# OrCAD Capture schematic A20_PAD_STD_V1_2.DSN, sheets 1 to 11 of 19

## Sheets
1 P11: POWER2: size A3; title: A20_PAD_STD; rev: V1.2; note: POWER2
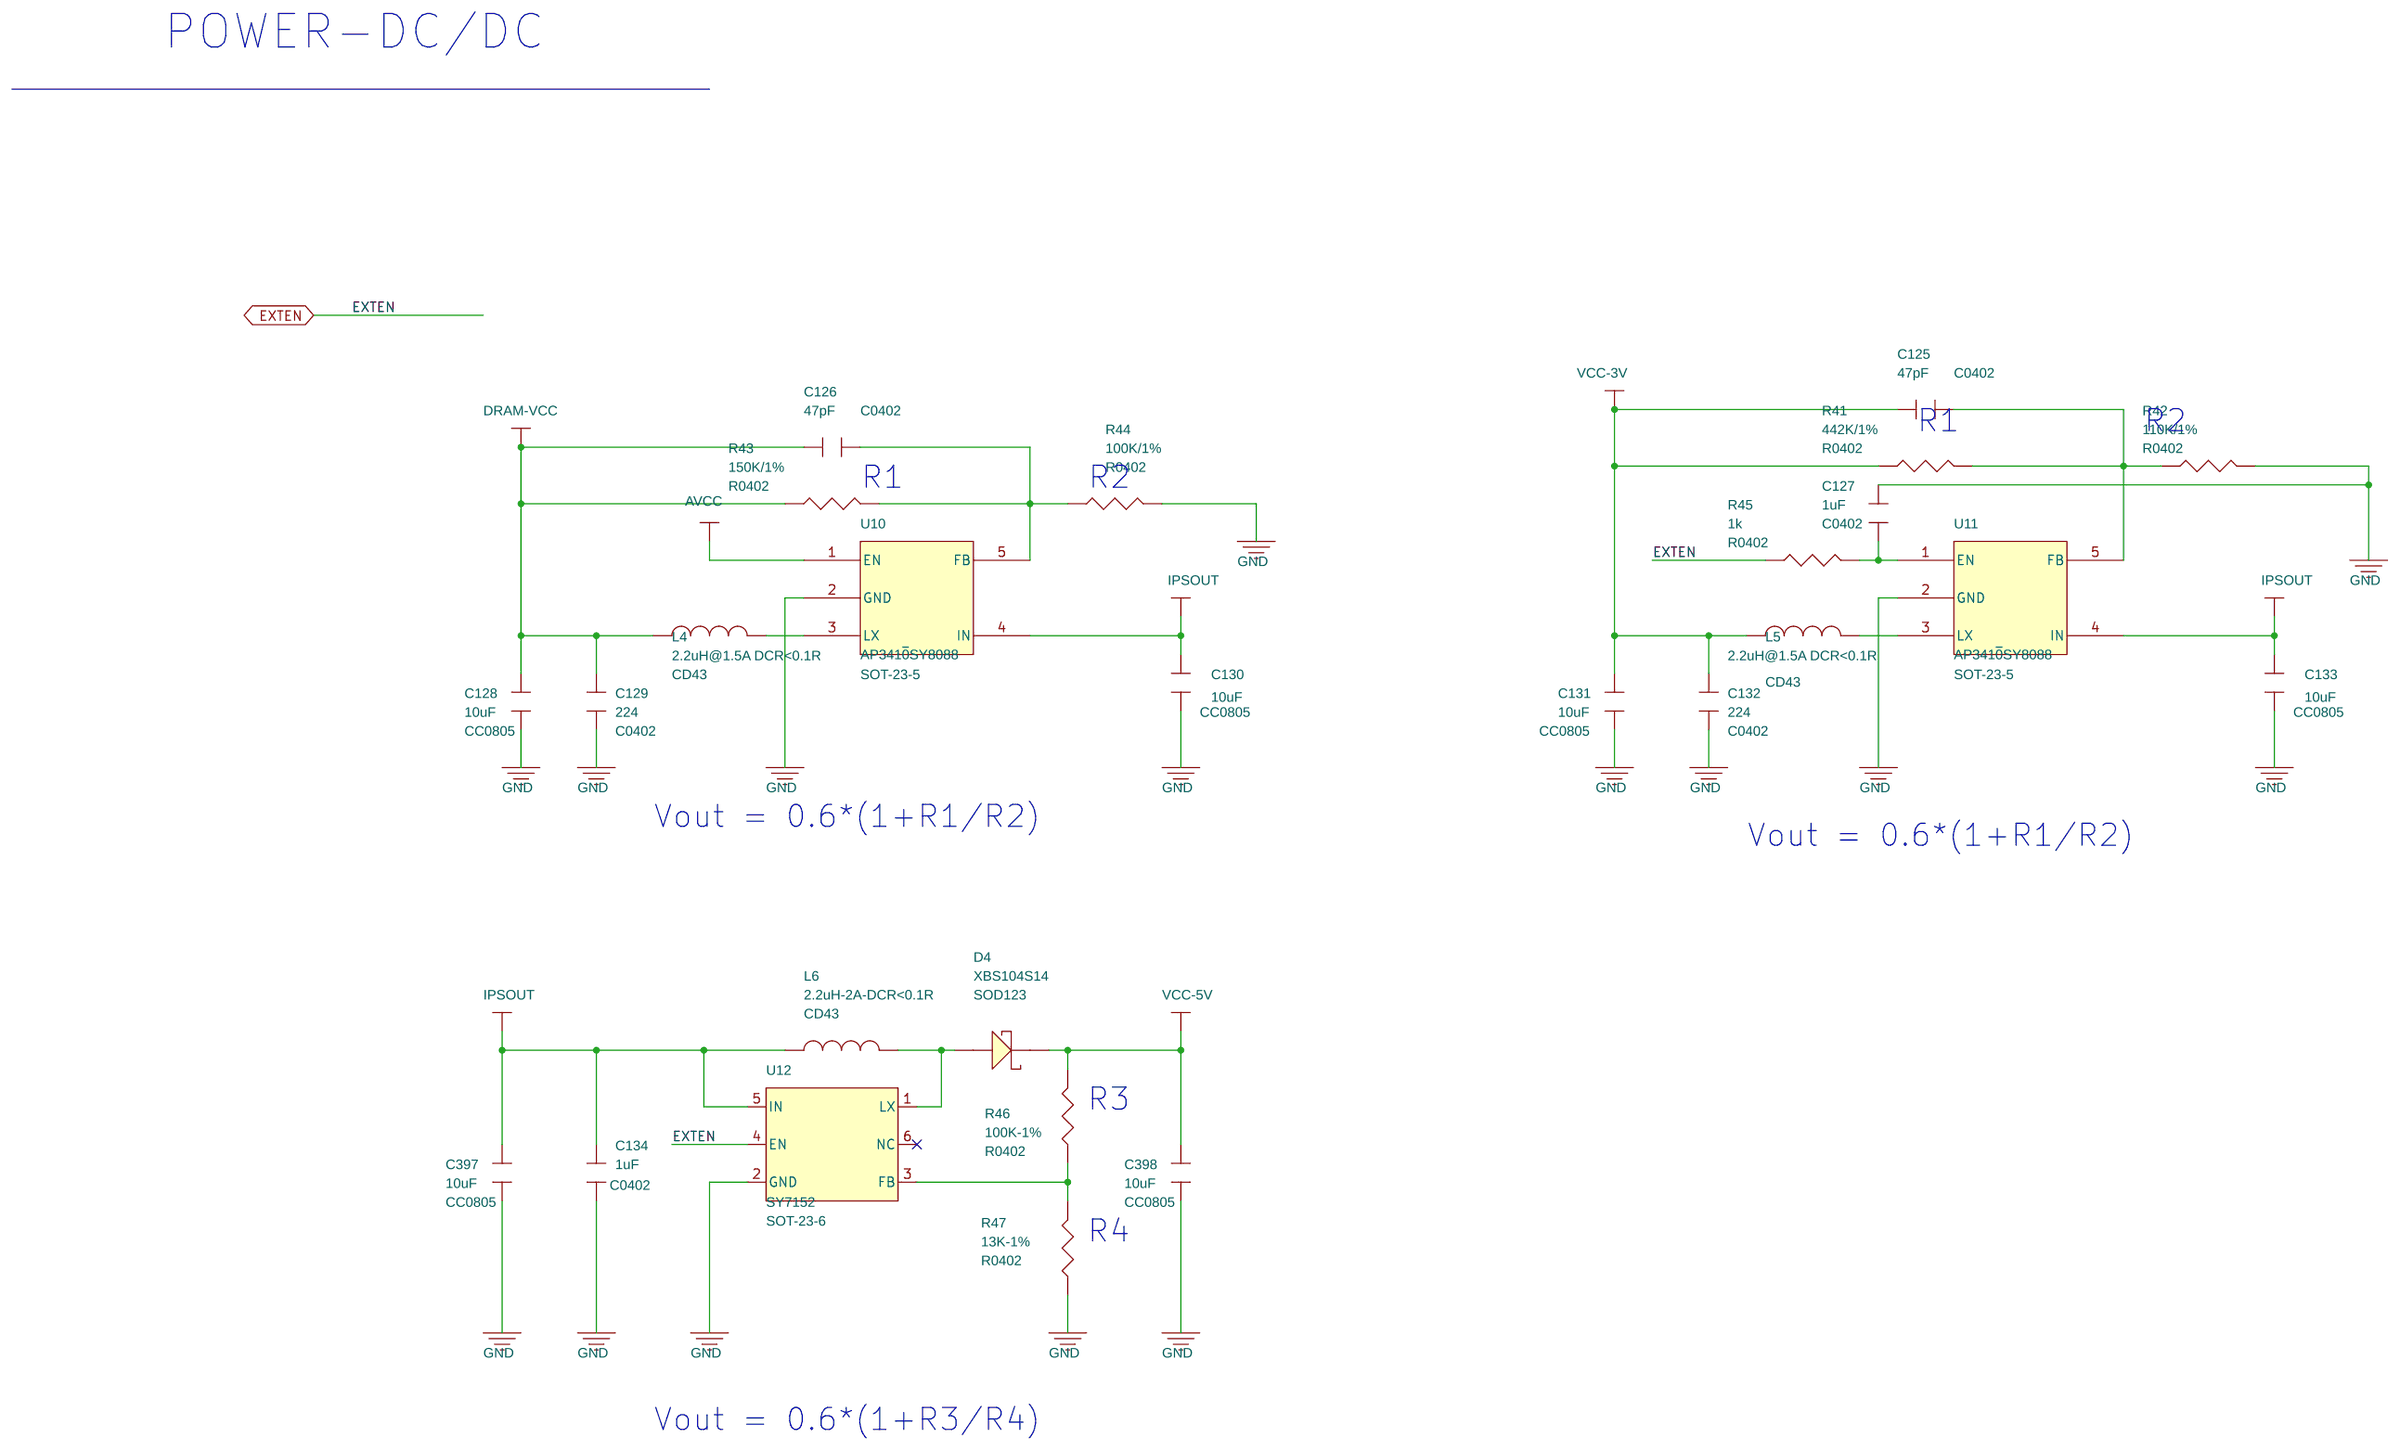
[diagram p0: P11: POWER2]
2 P06: CPU2: size A3; note: CPU2
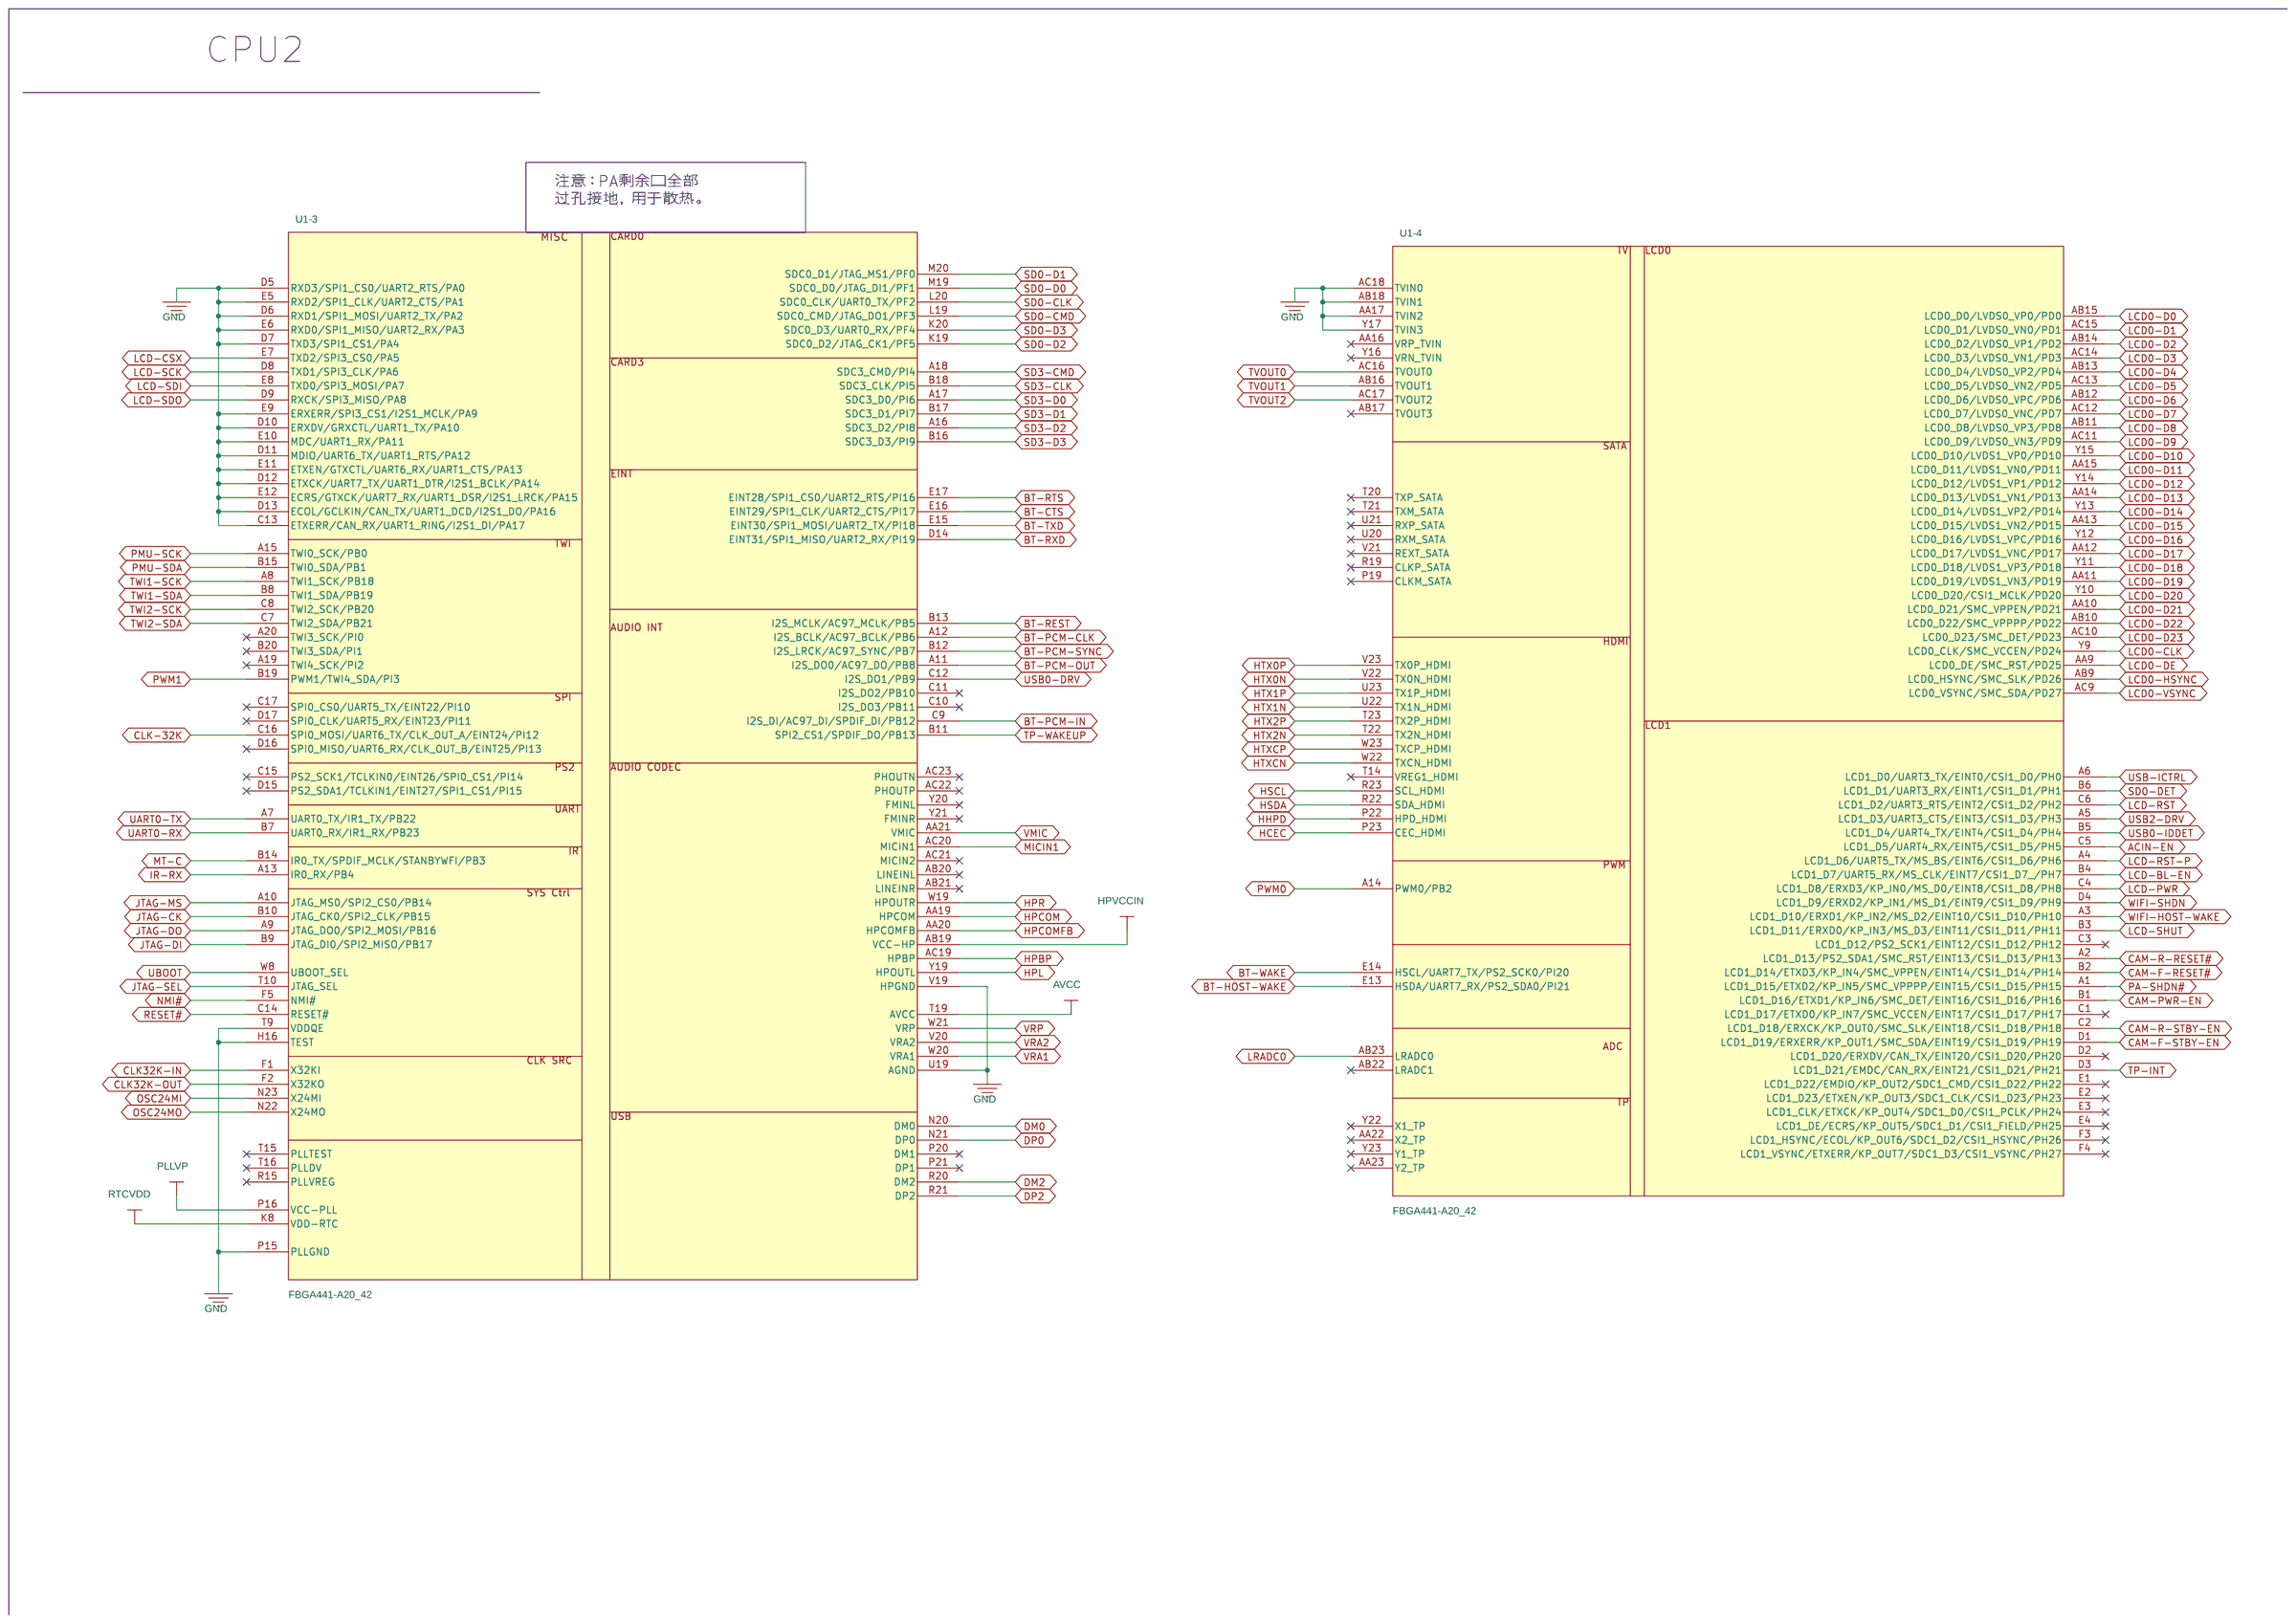
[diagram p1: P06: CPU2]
3 P18: USB: size A3; note: USB
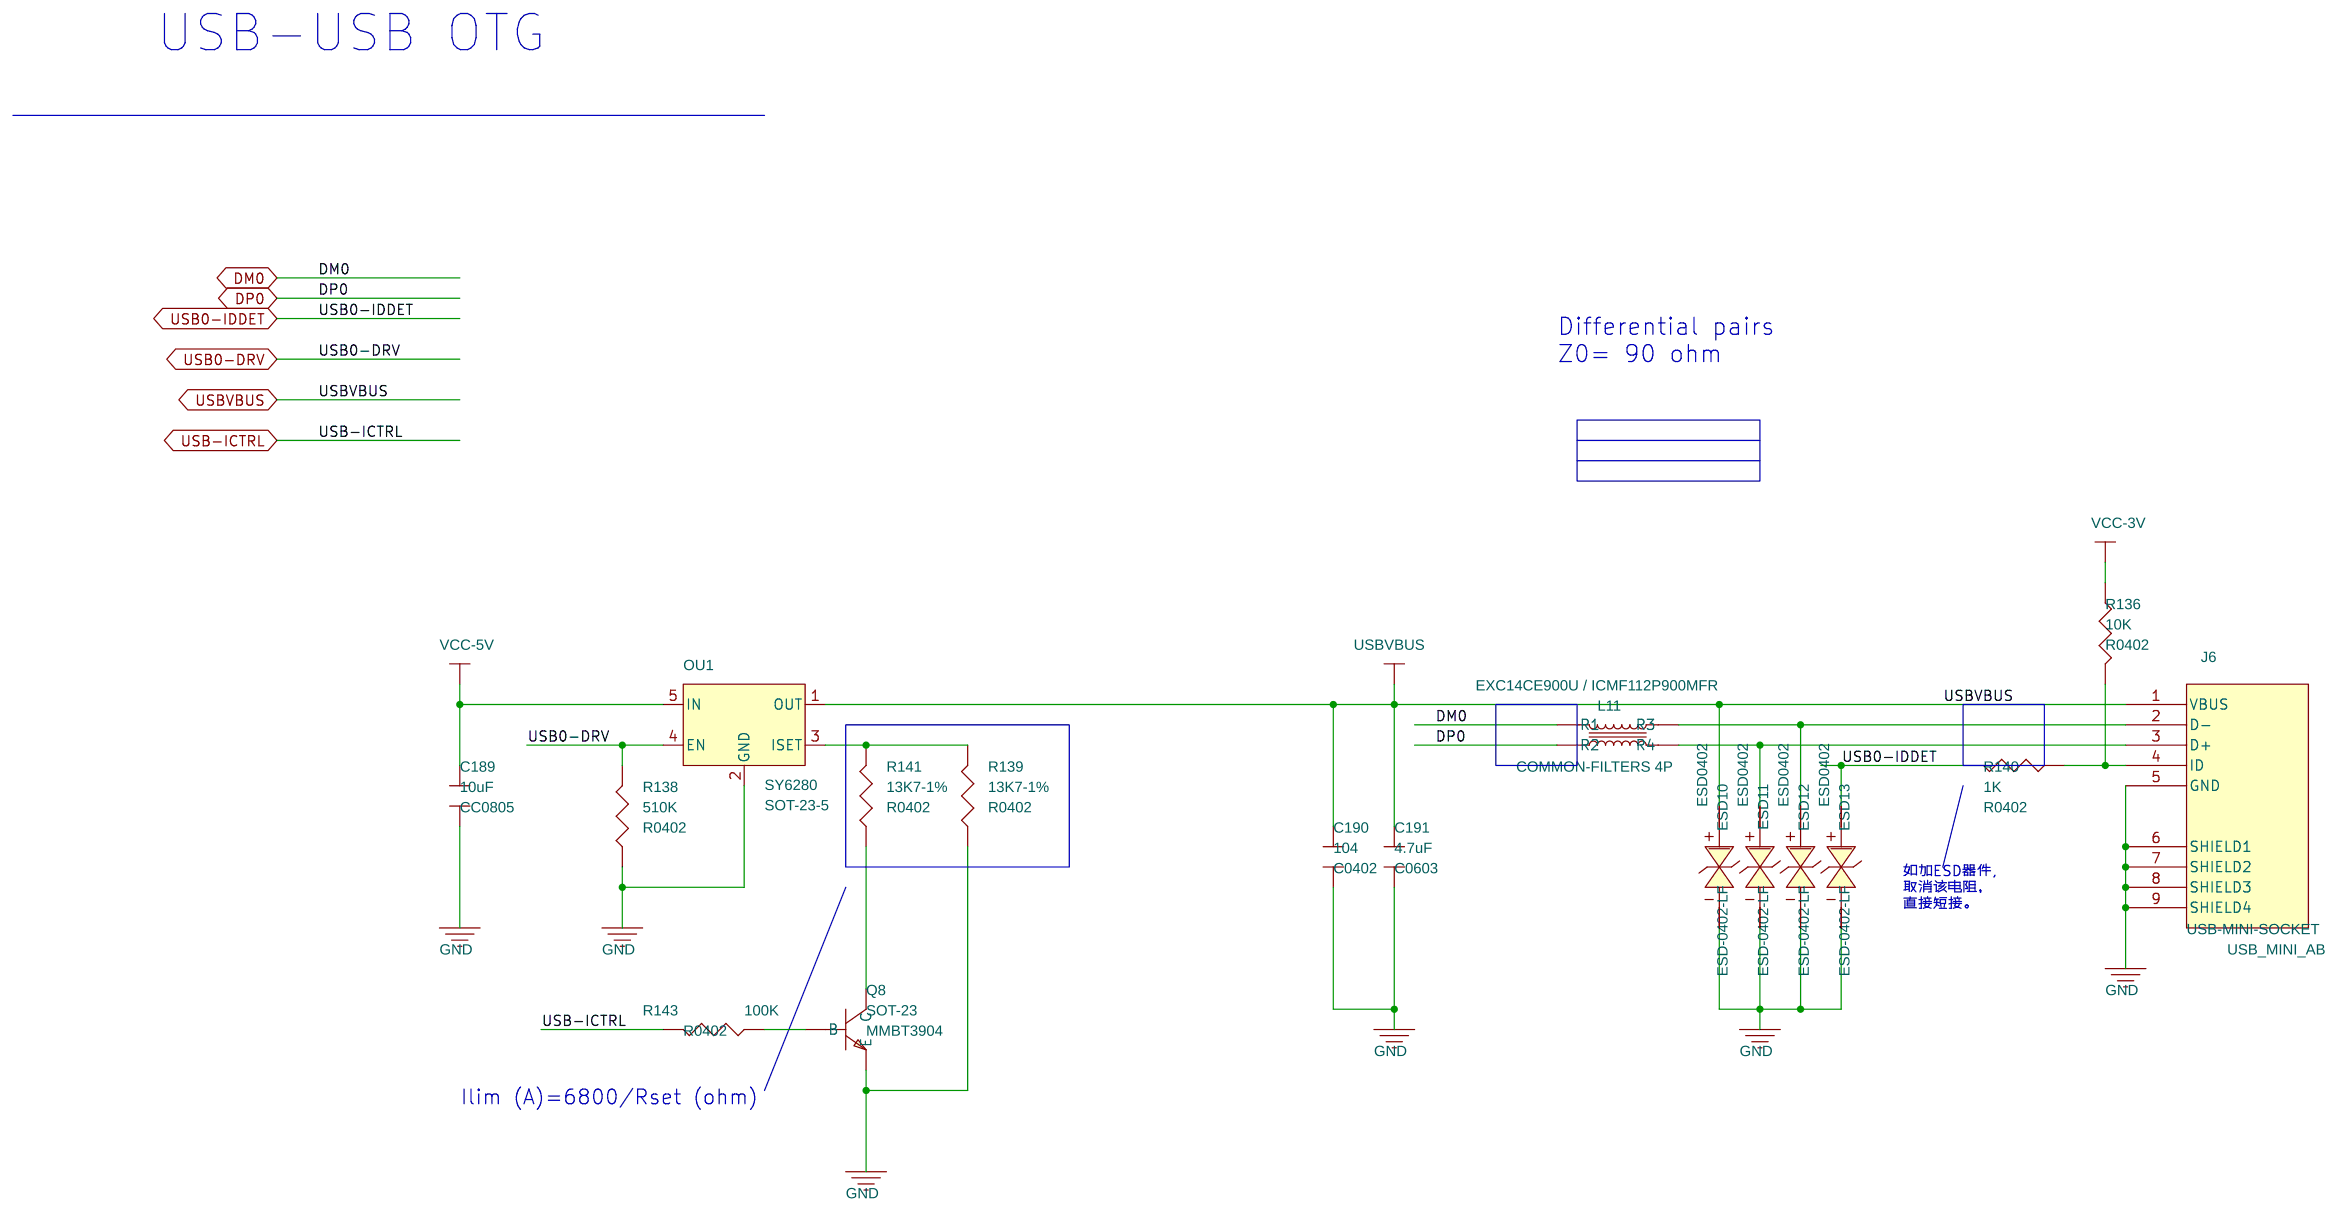
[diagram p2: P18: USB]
4 P16: LCD: size A3; note: LCD
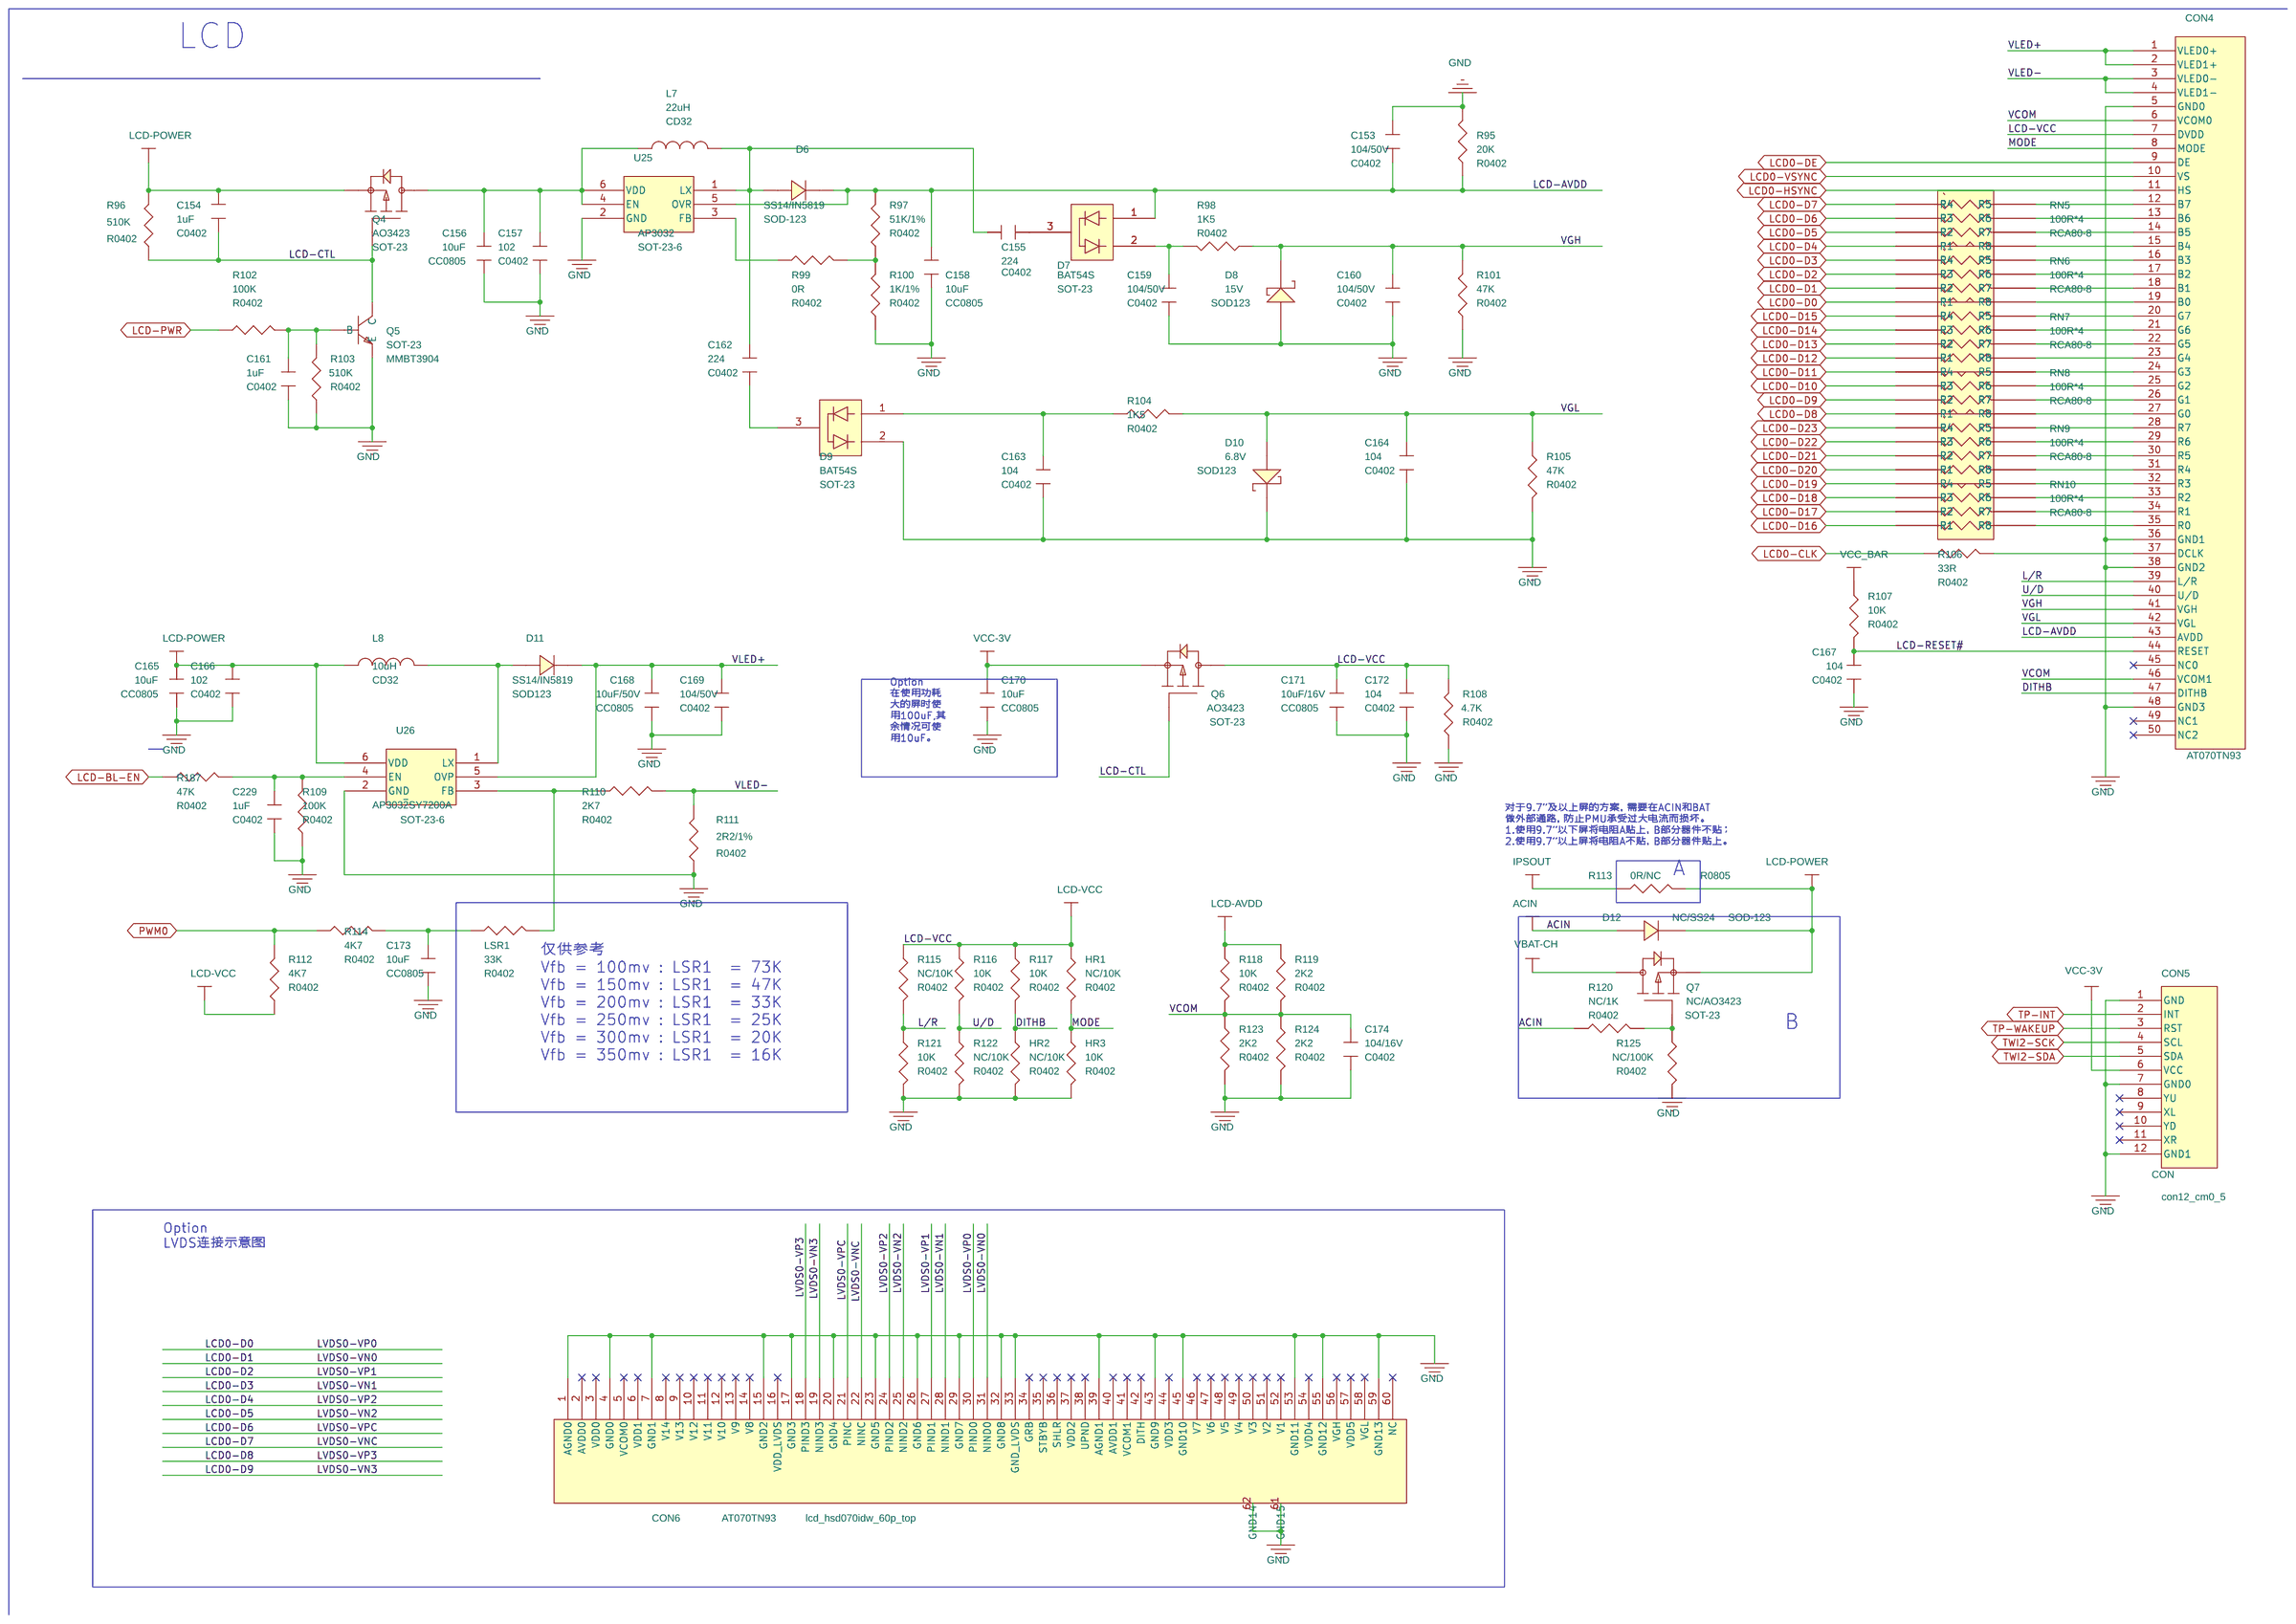
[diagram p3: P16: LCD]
5 P05: CPU1: size A3; note: CPU1
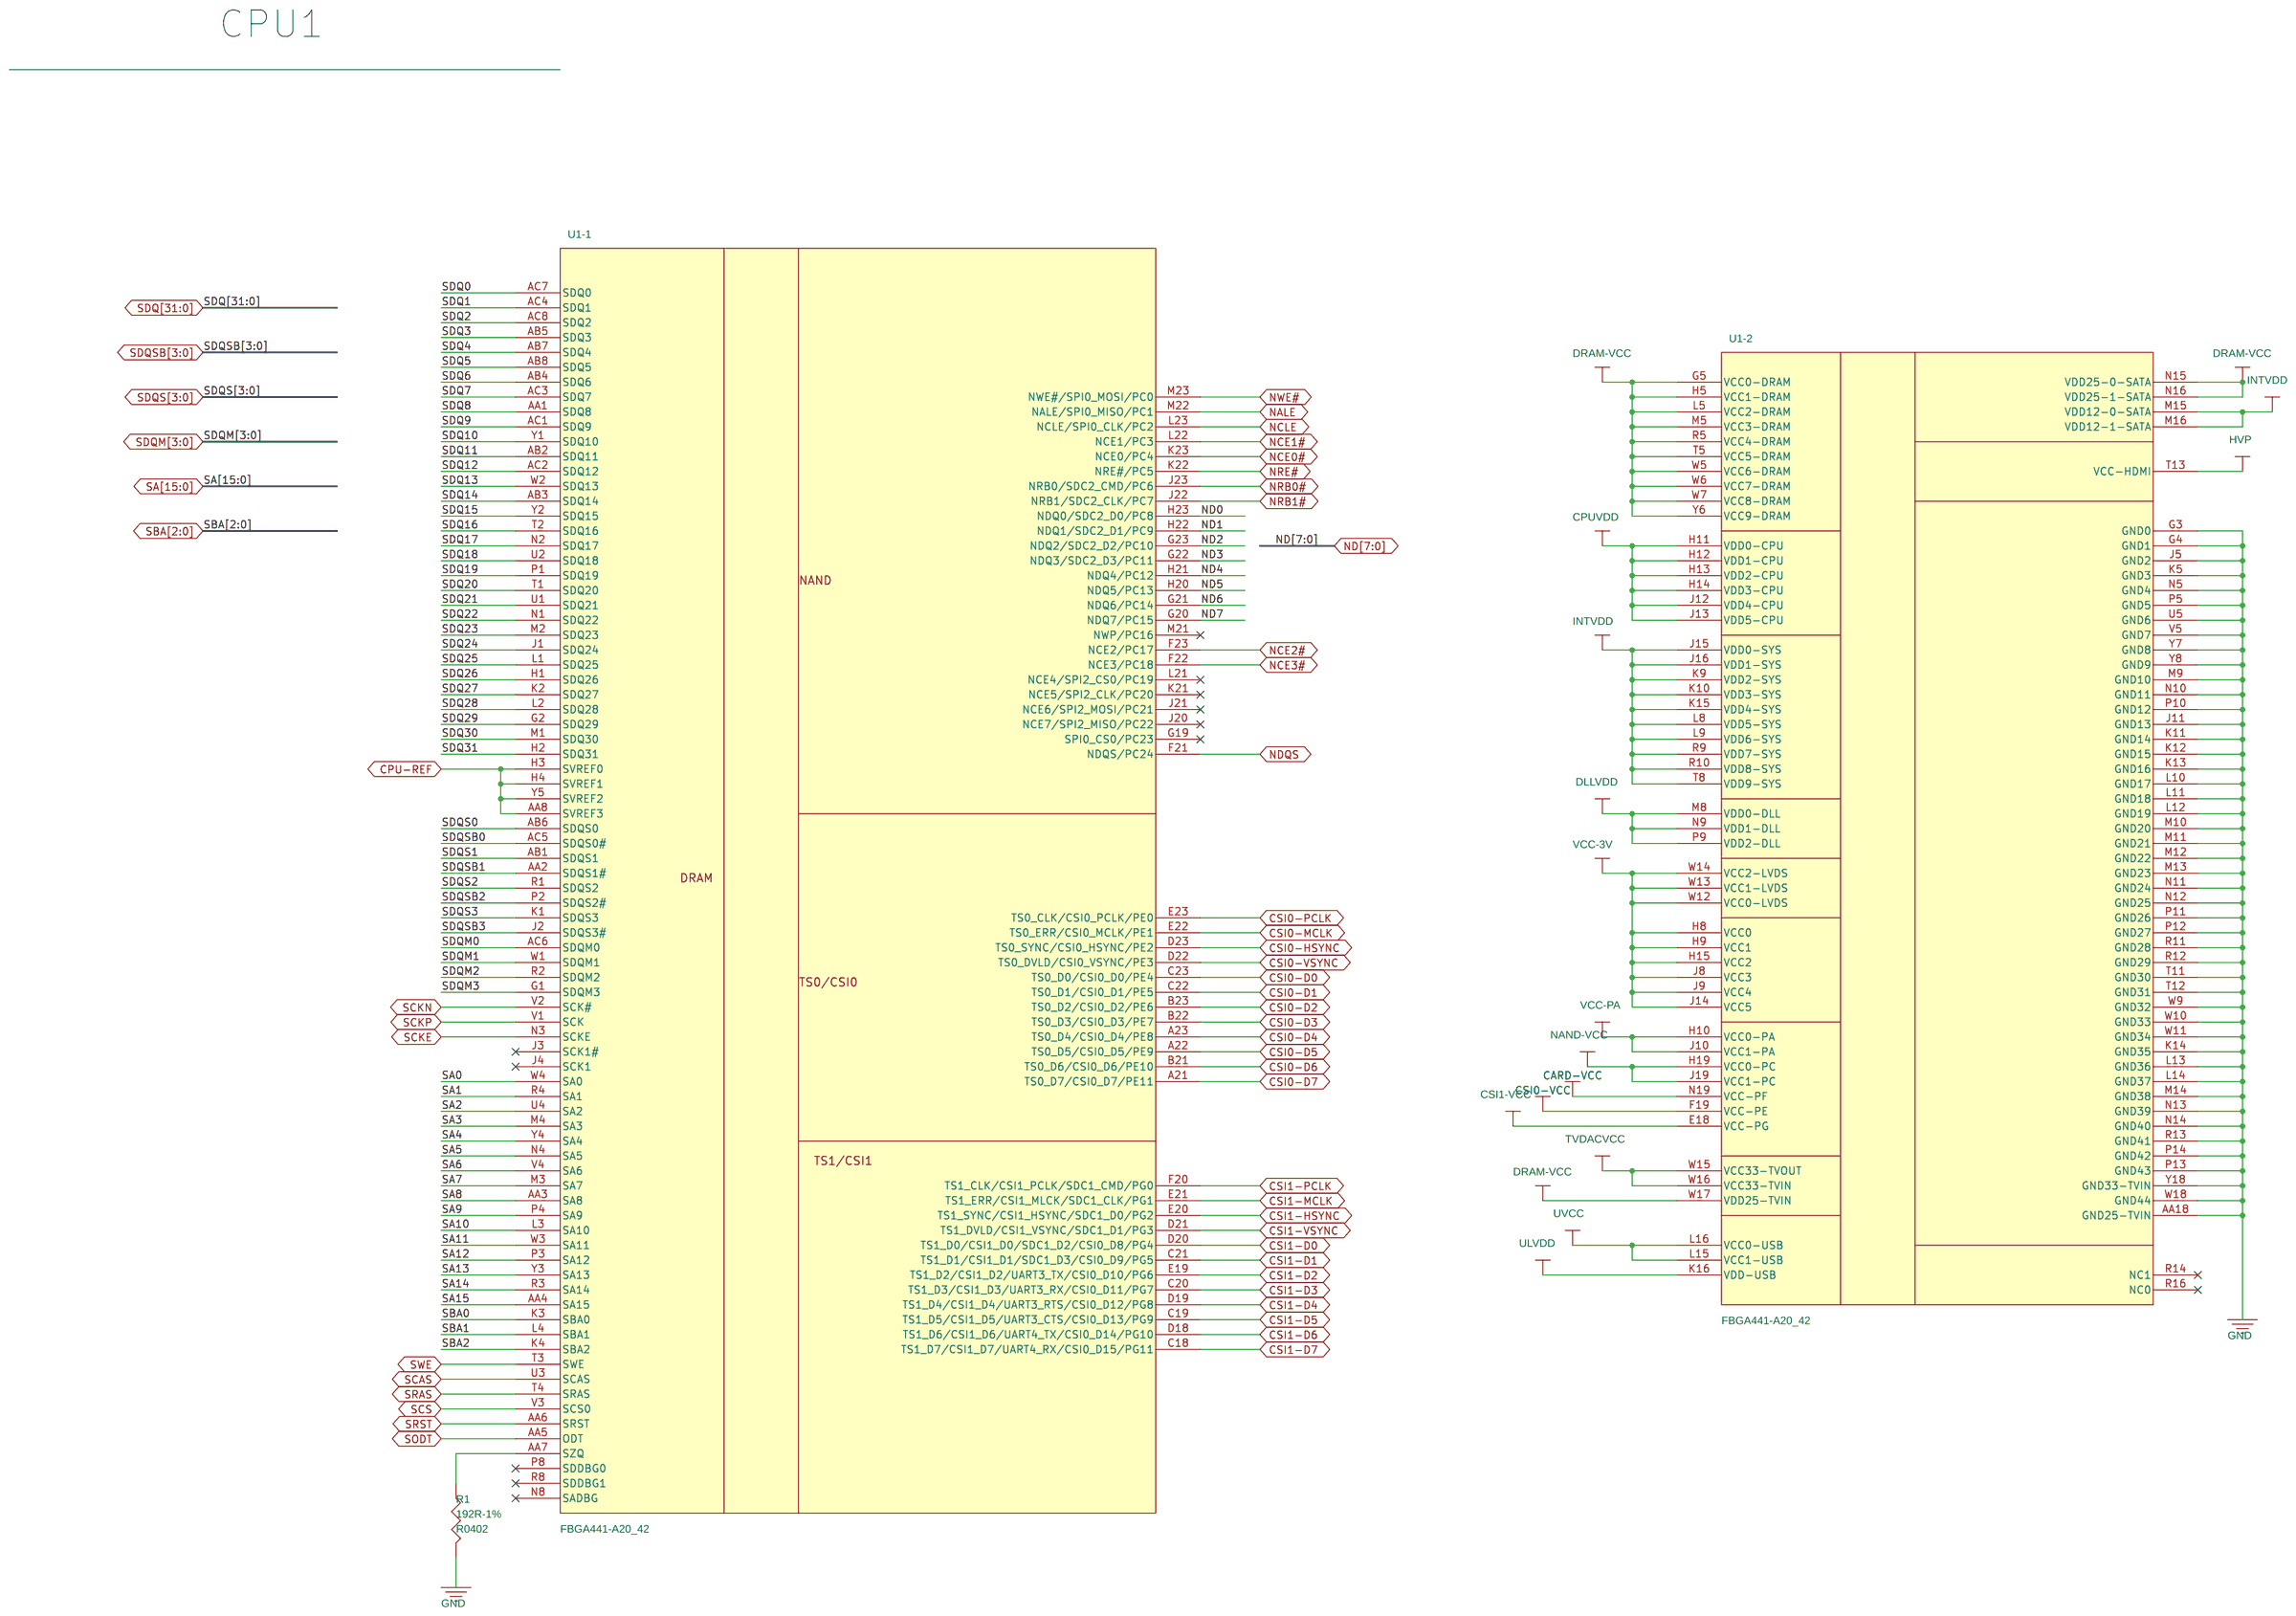
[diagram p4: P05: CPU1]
6 P02: BLOCK: note: BLOCK
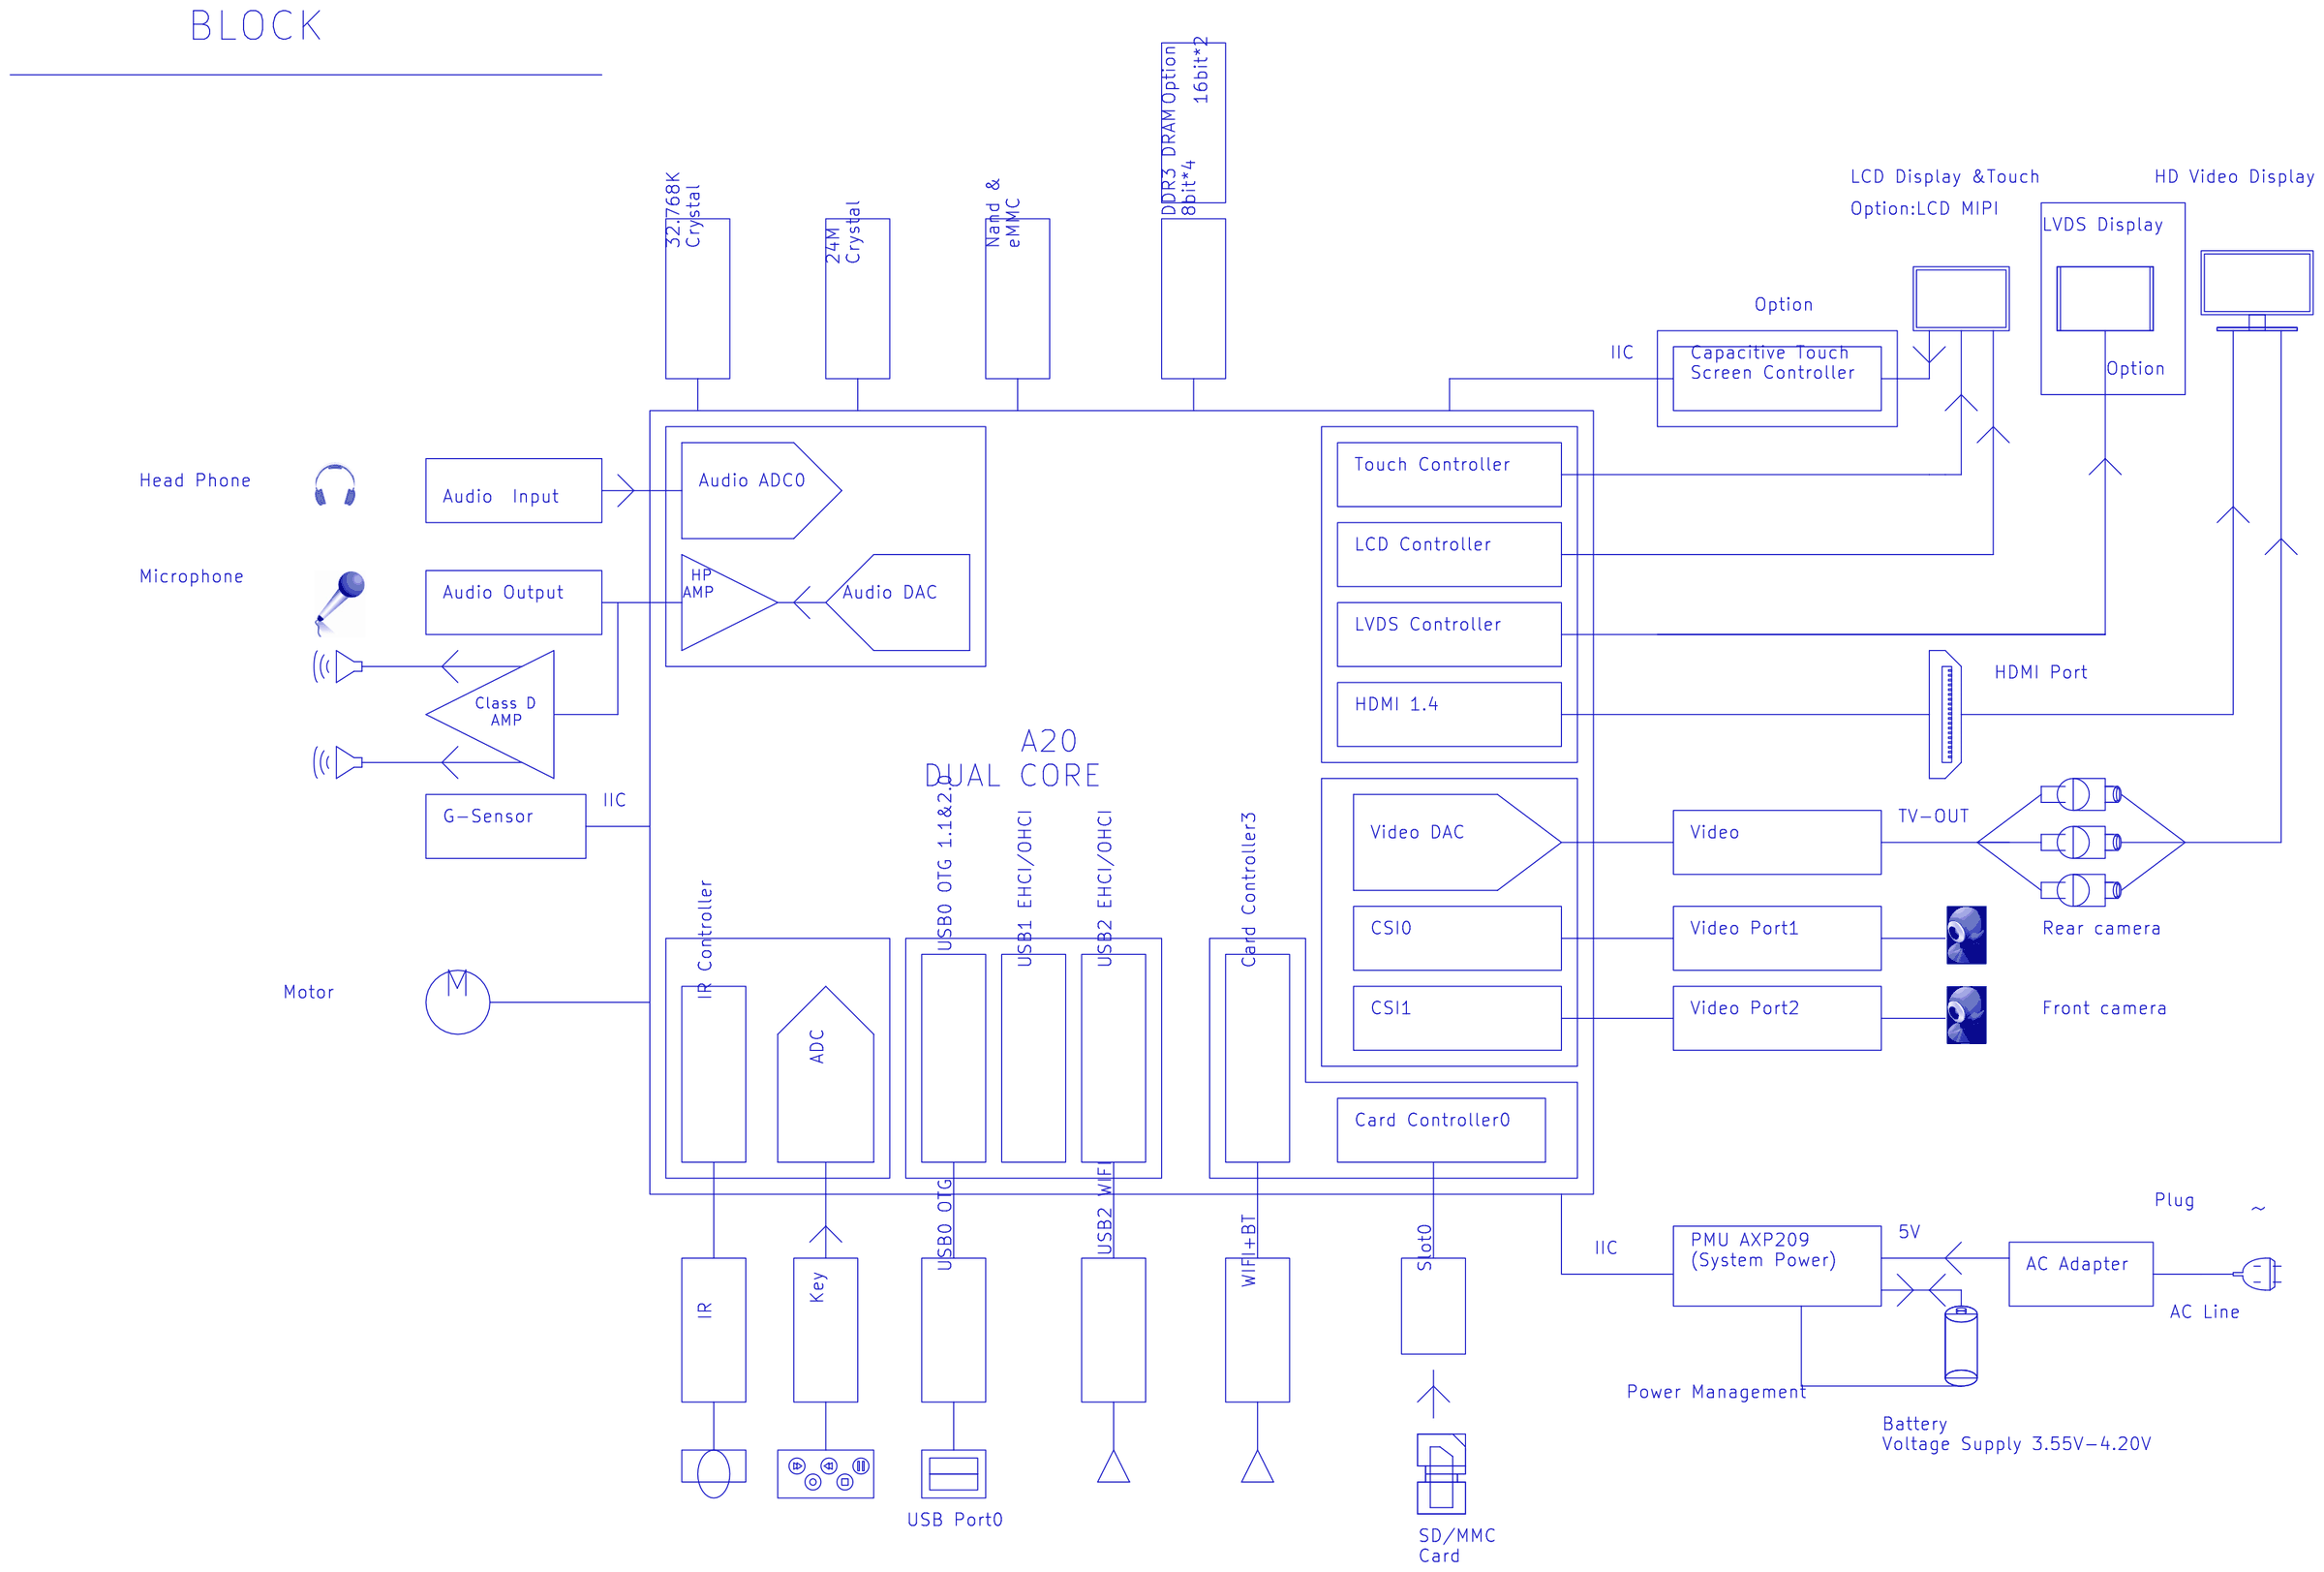
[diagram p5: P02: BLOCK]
7 P01: COVER: note: COVER
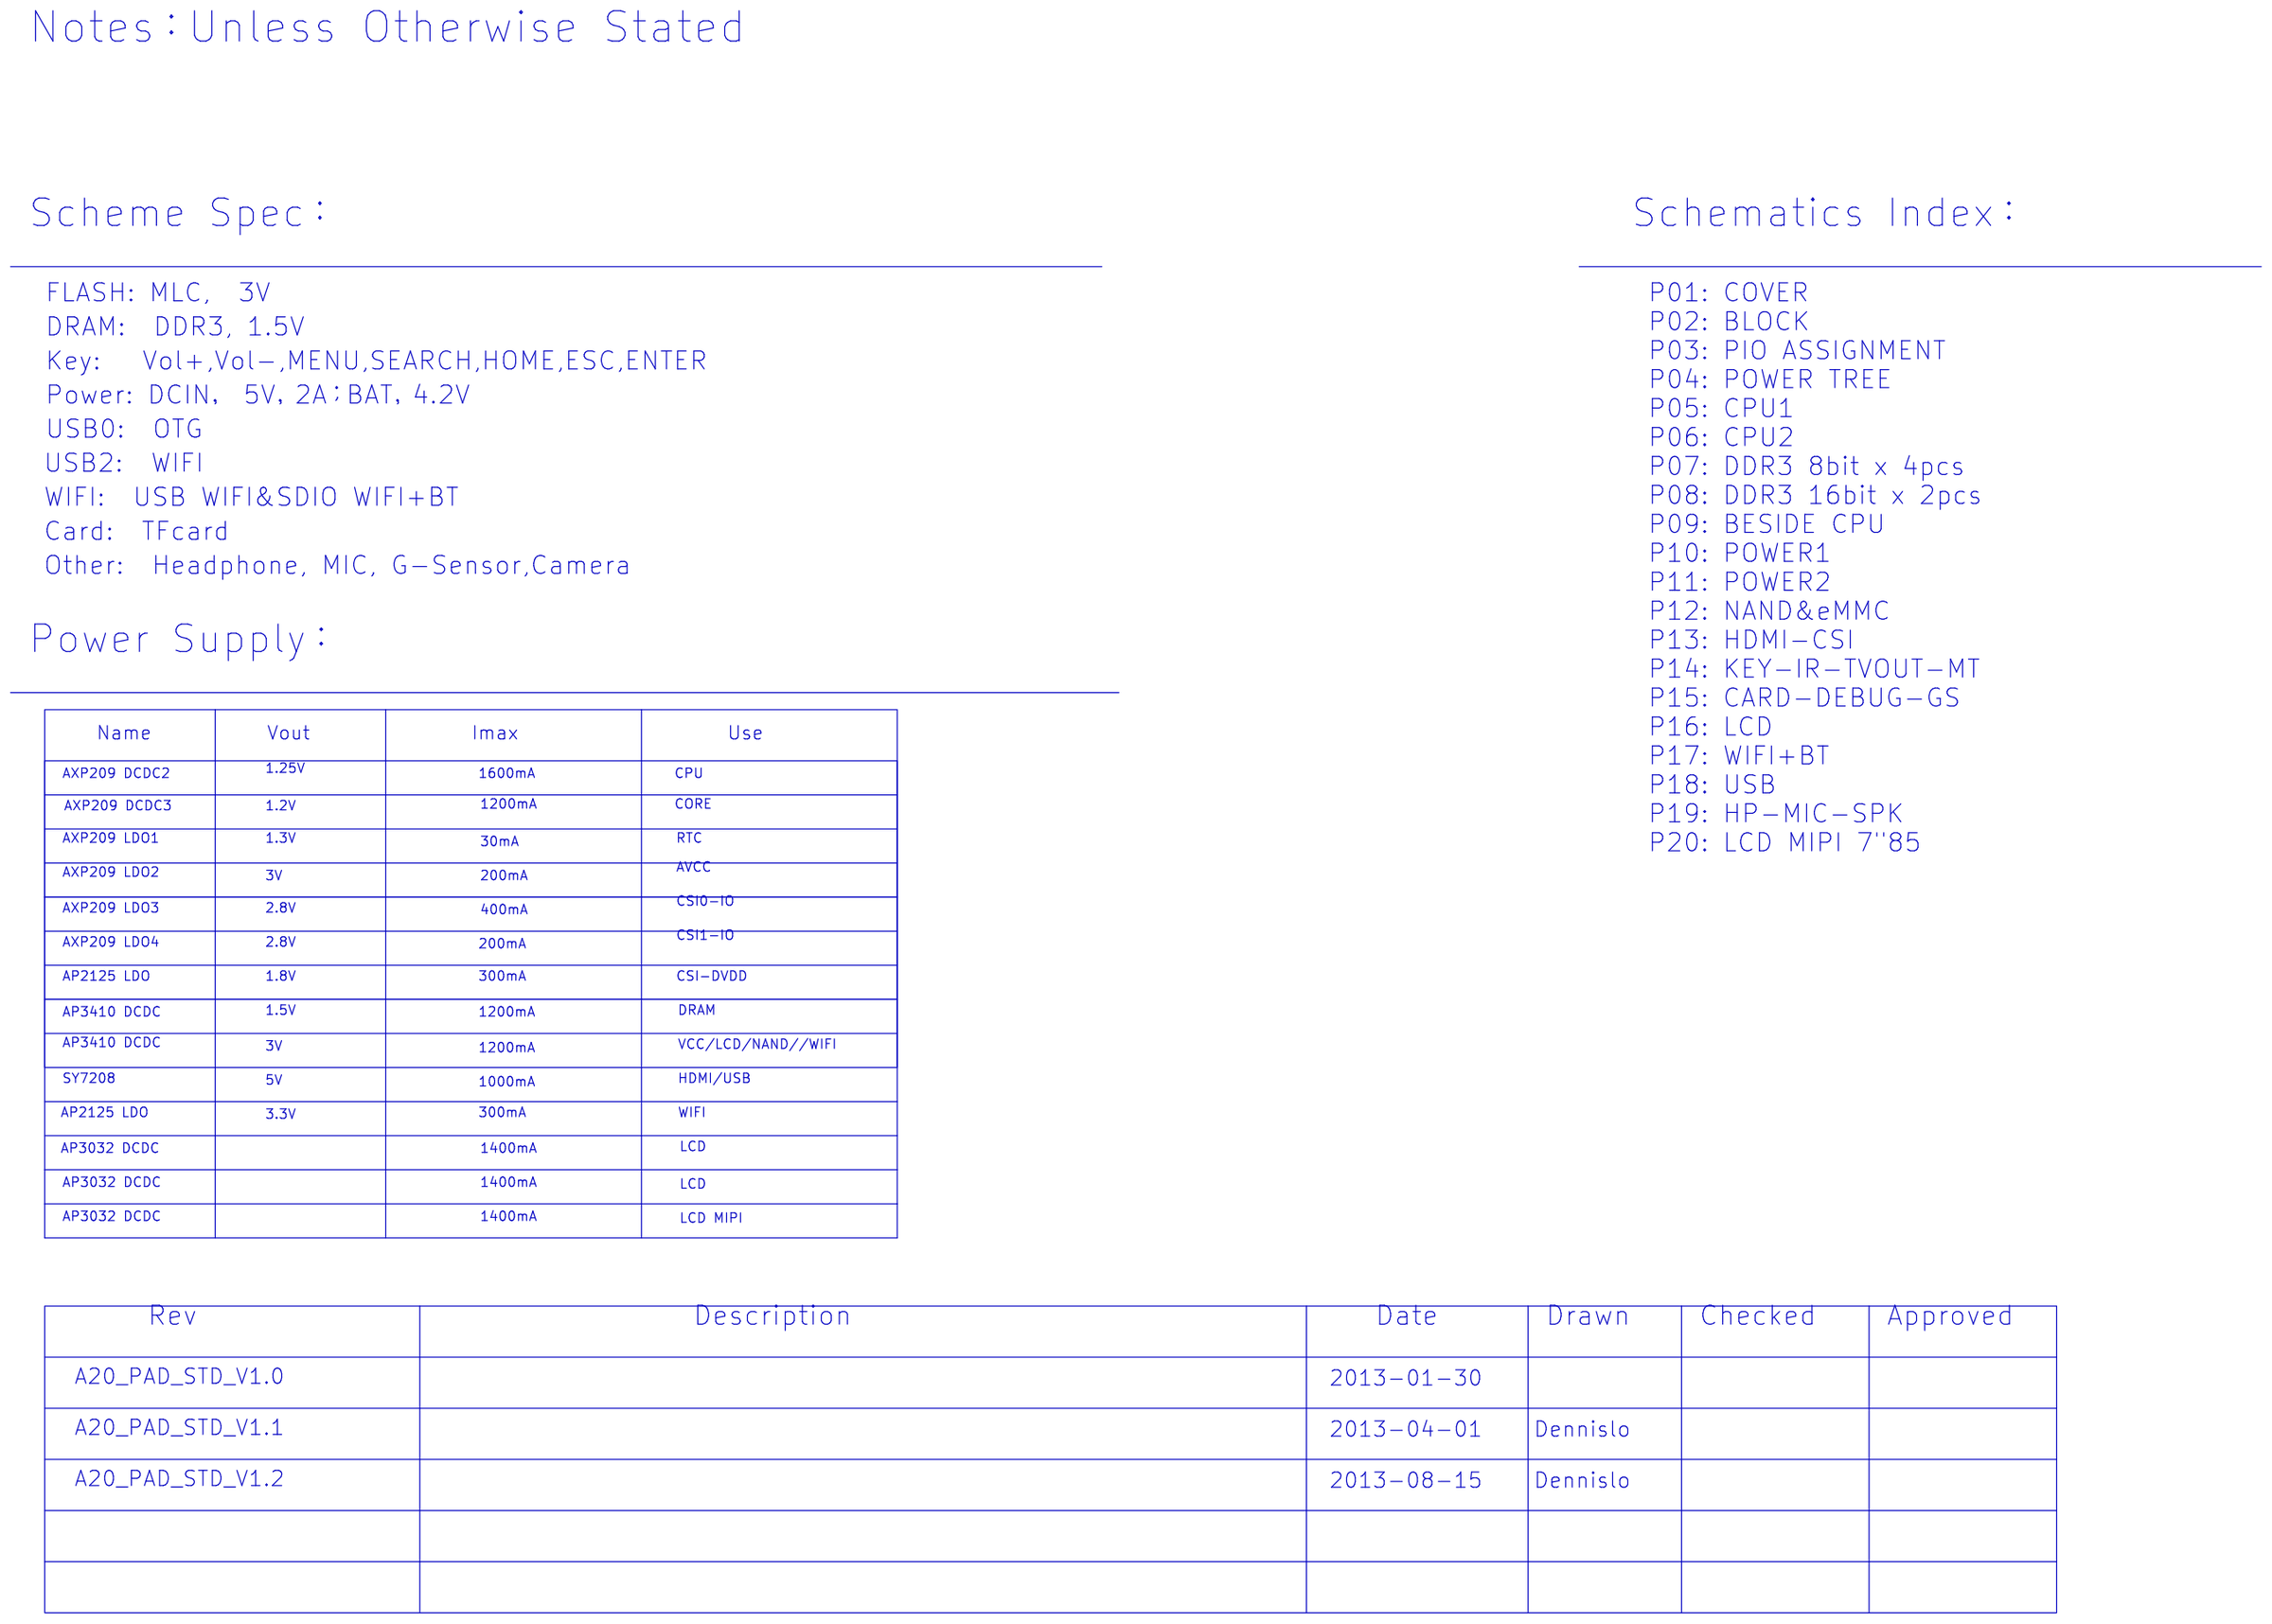
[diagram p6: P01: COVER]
8 P10: POWER1: size A3; note: POWER1
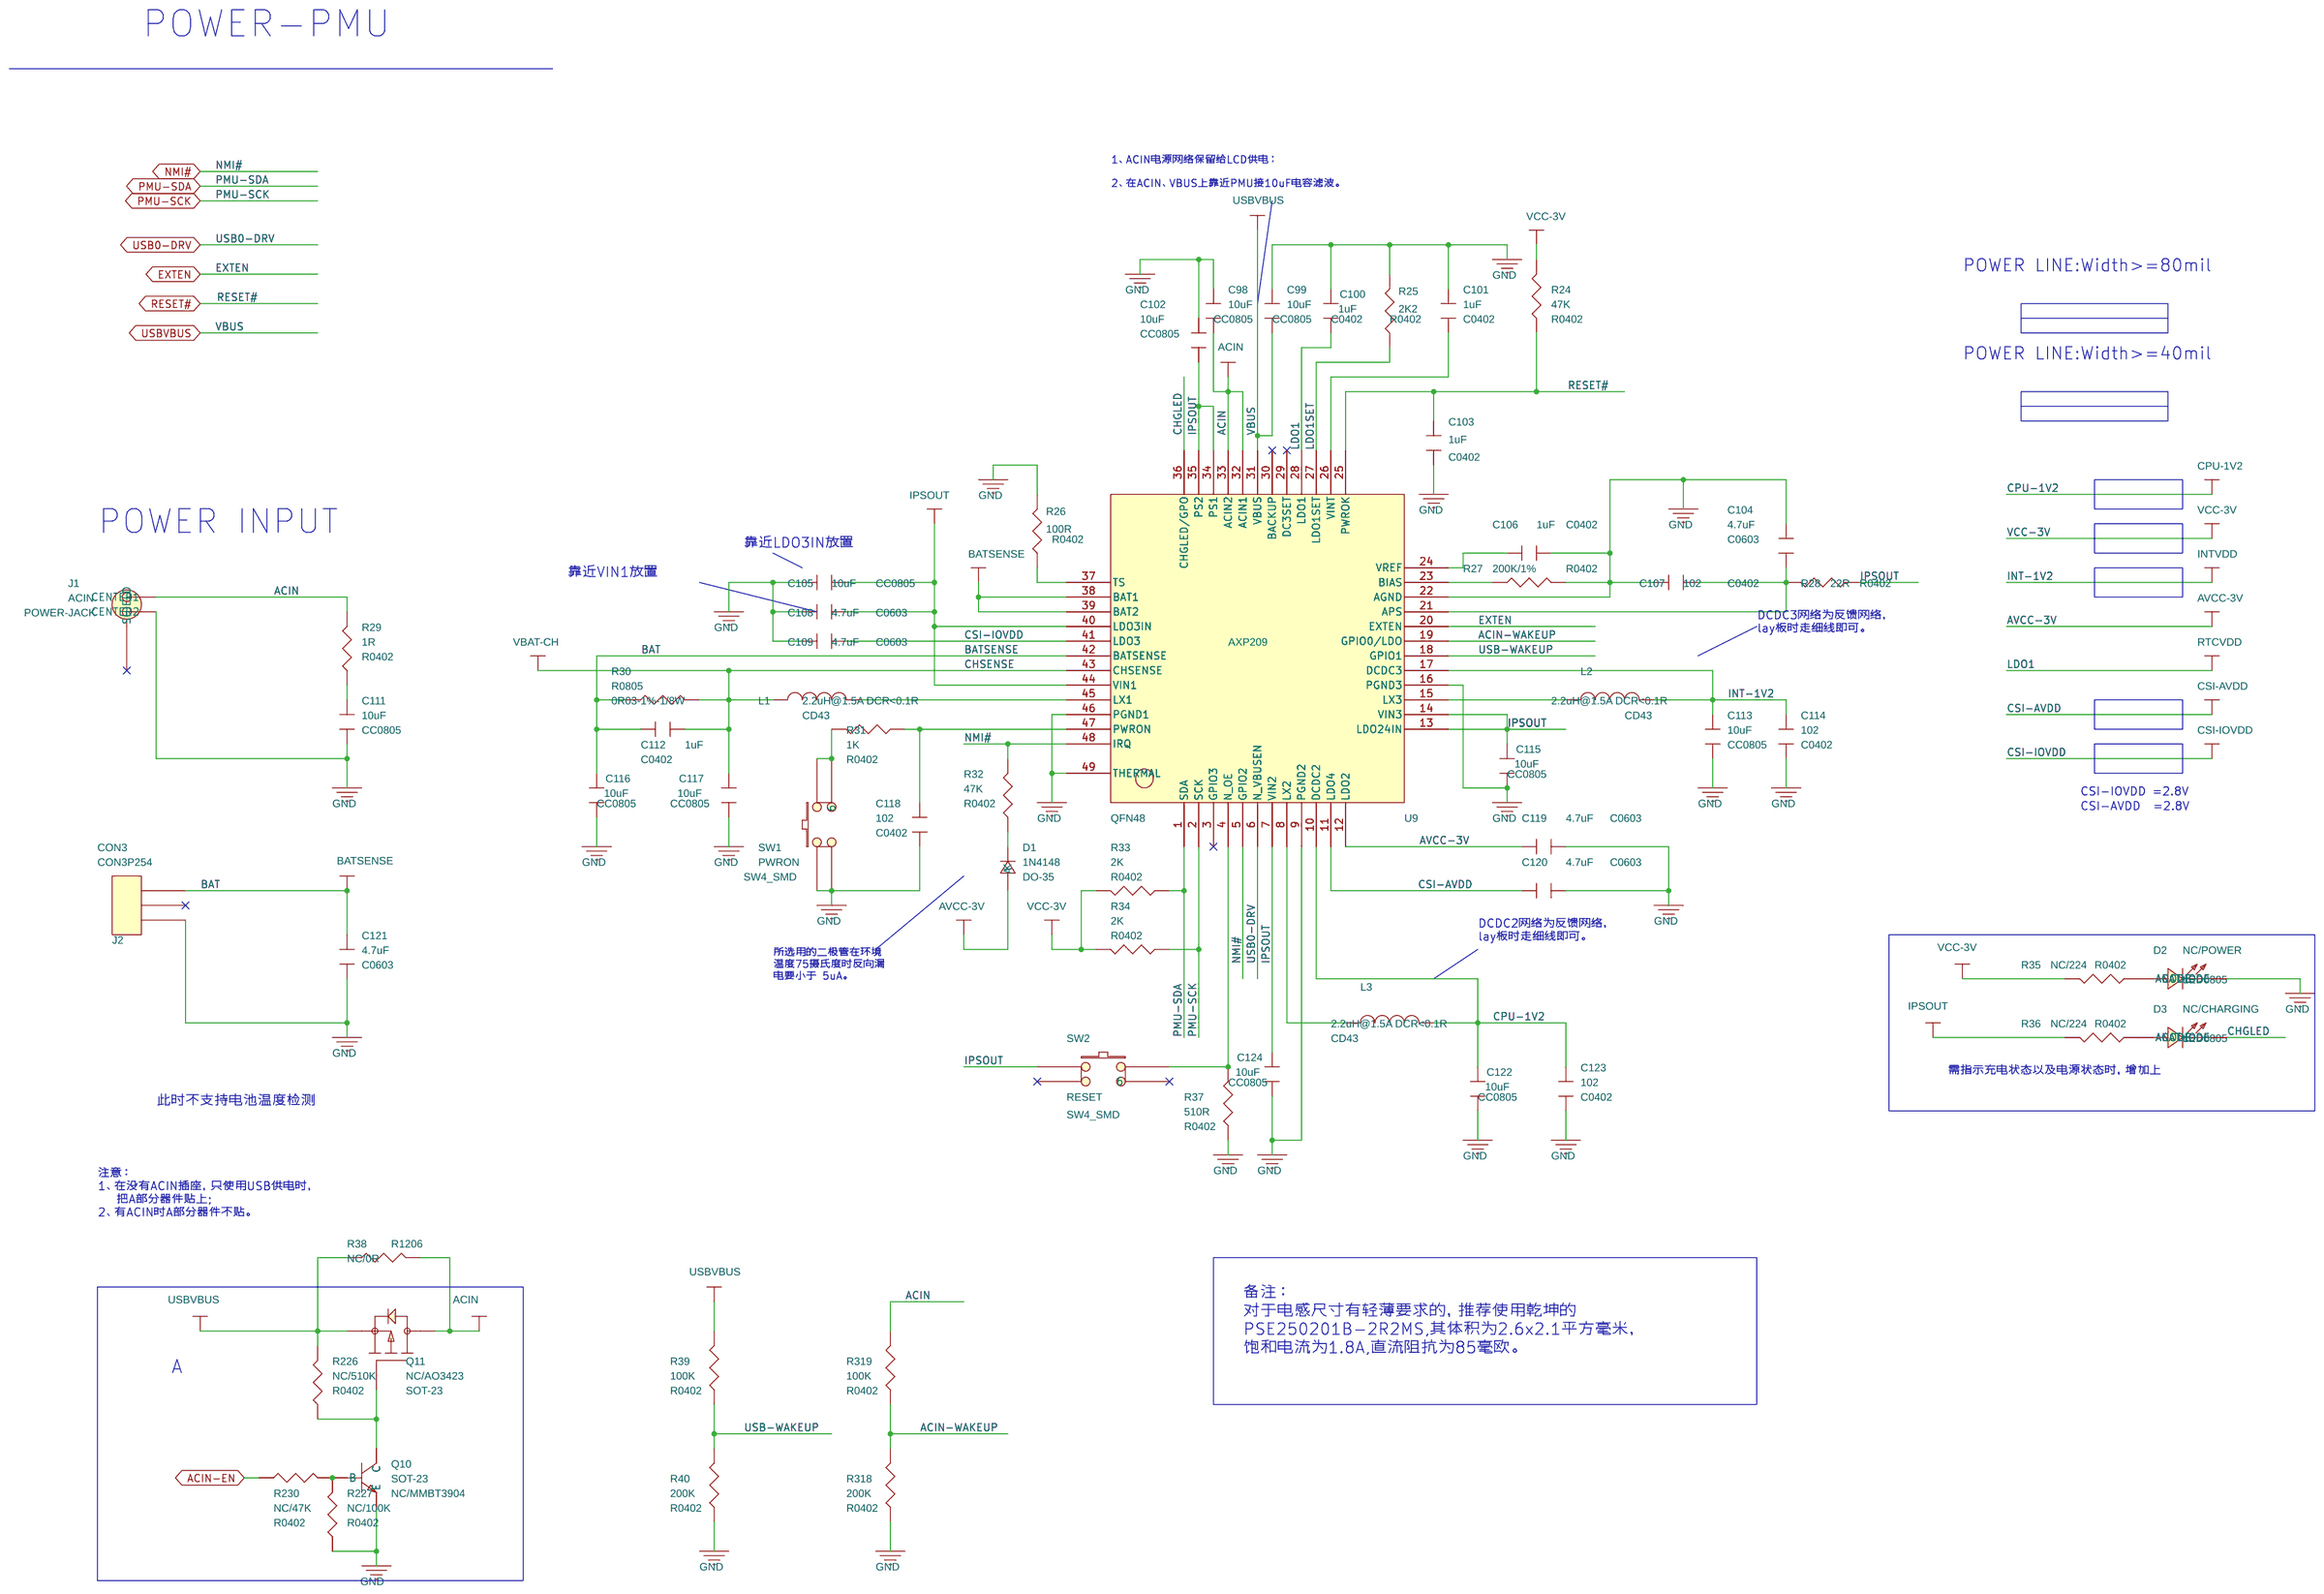
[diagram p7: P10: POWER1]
9 P04: POWER TREE: note: POWER
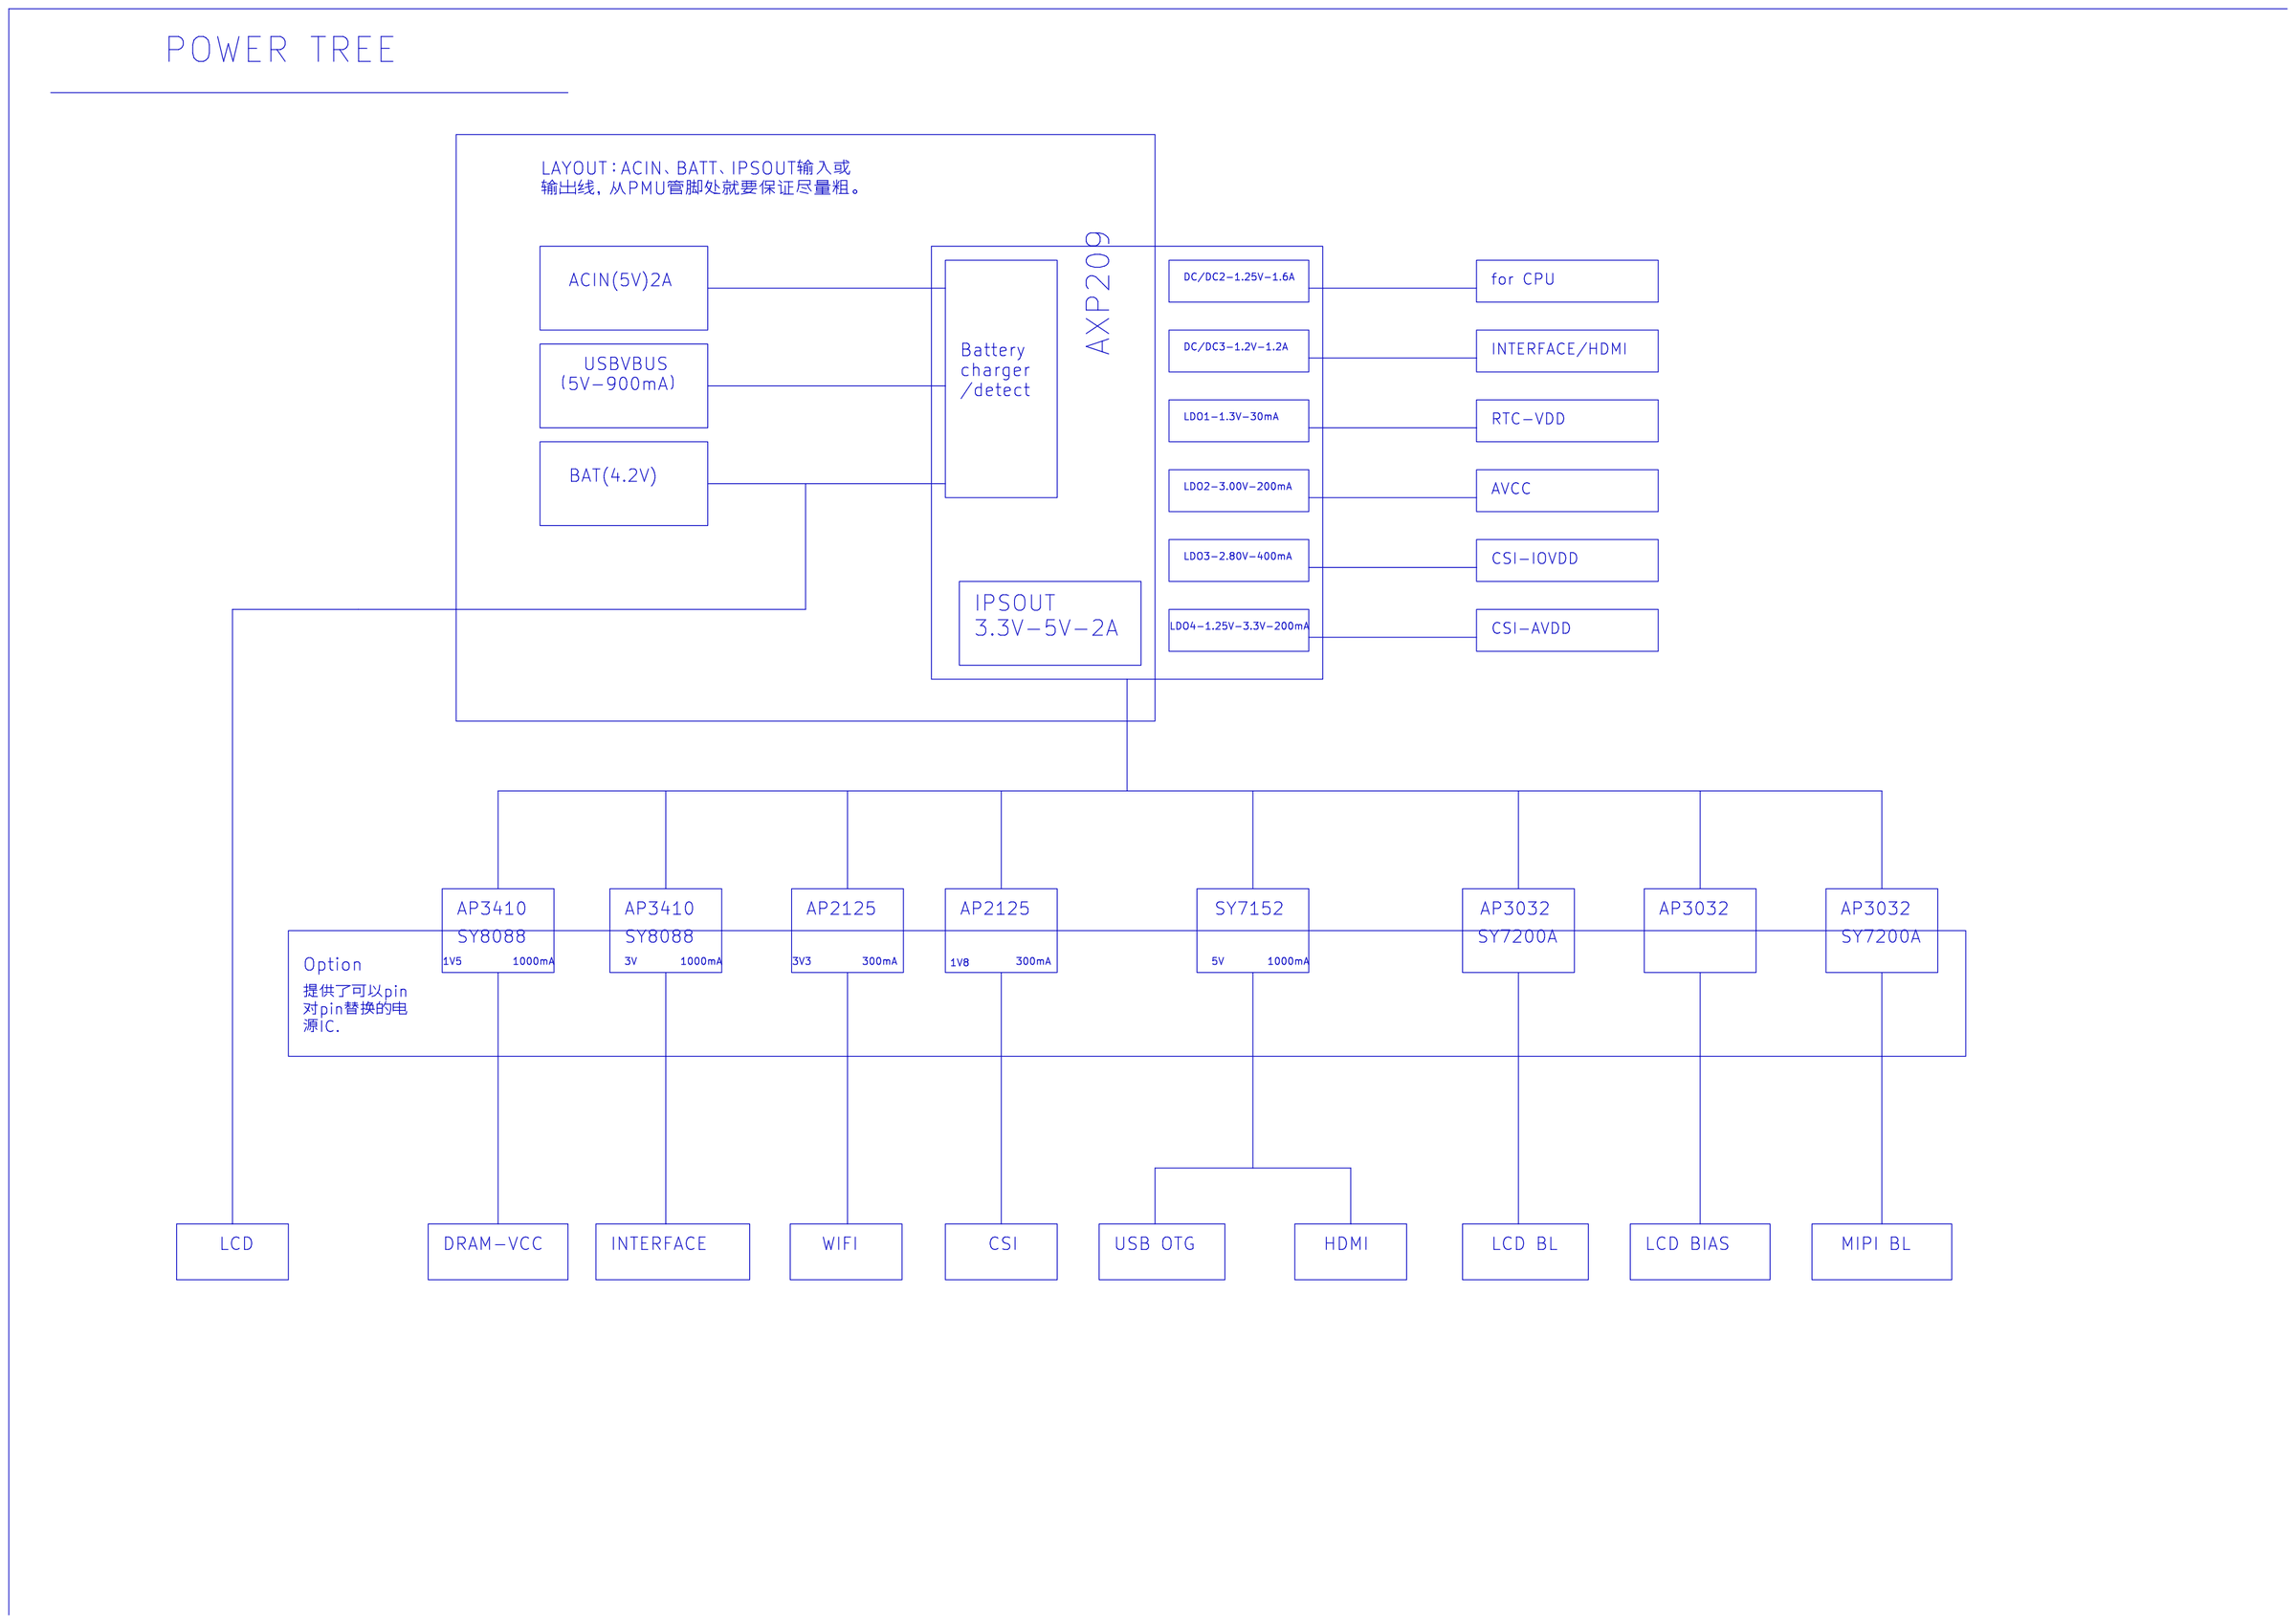
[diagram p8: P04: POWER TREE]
10 P13: HDMI-CSI: size A3; note: HDMI-CSI
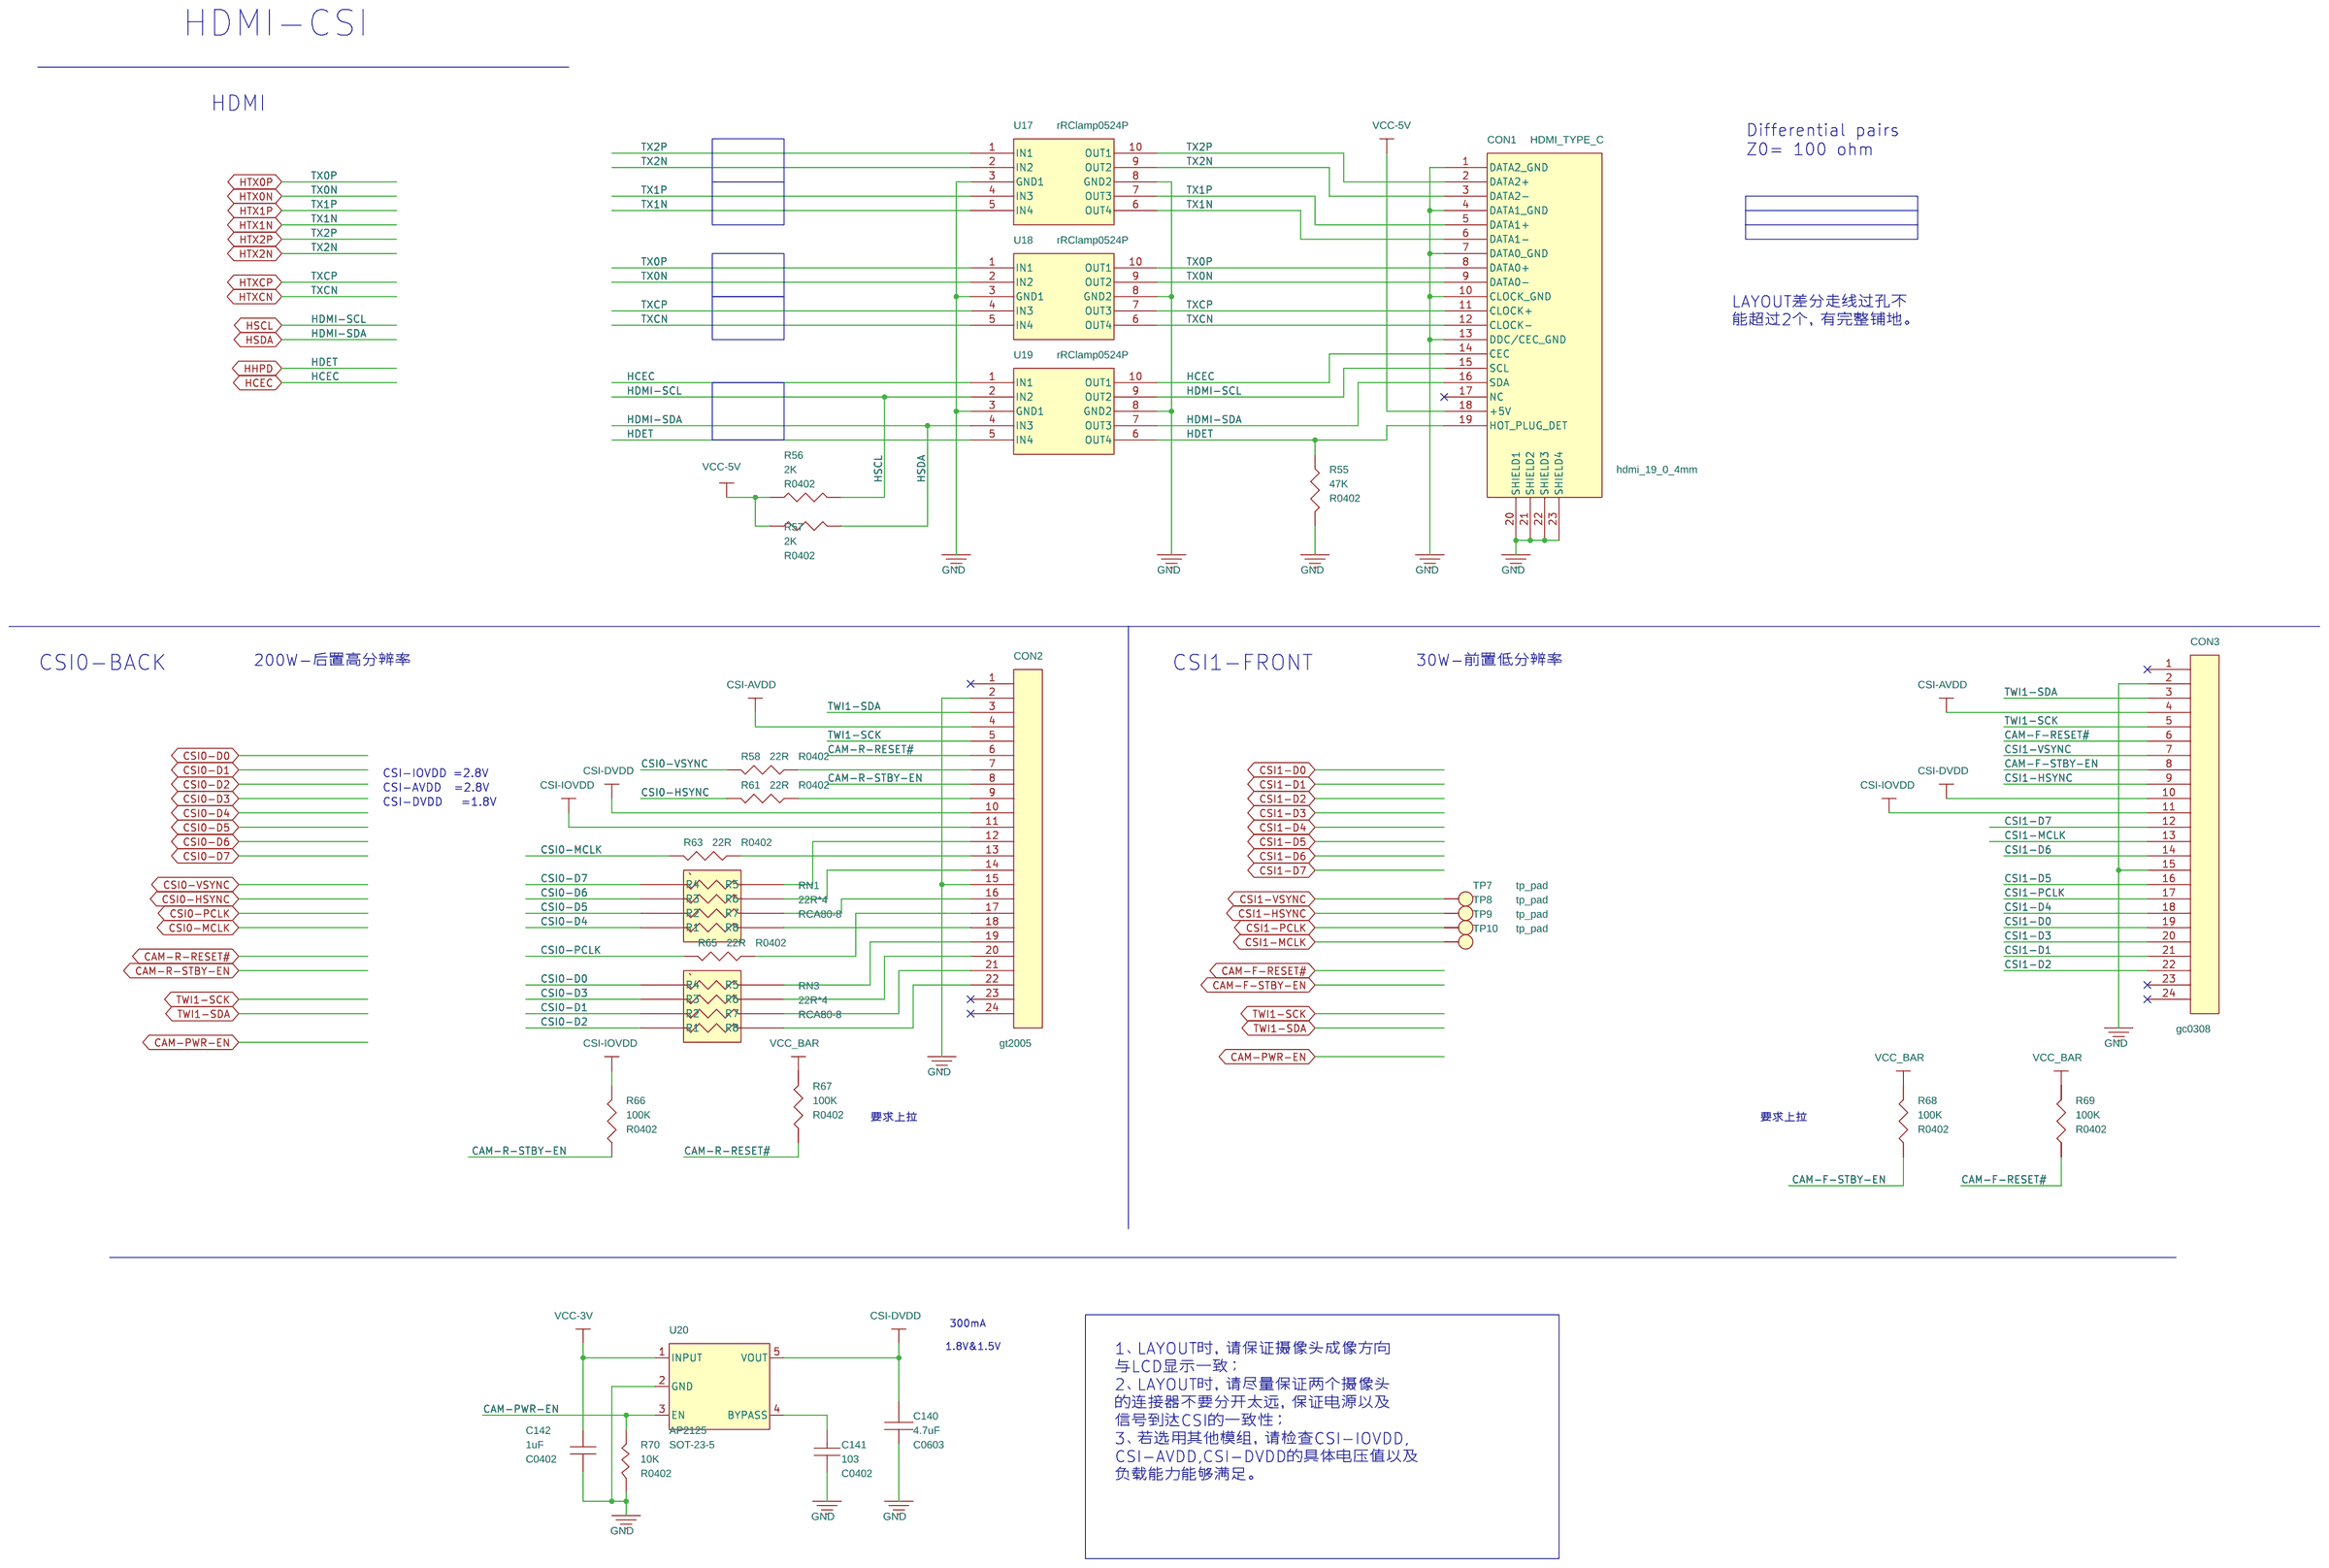
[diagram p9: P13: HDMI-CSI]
11 P17: WIFI-BT: size A3; note: WIFI-BT
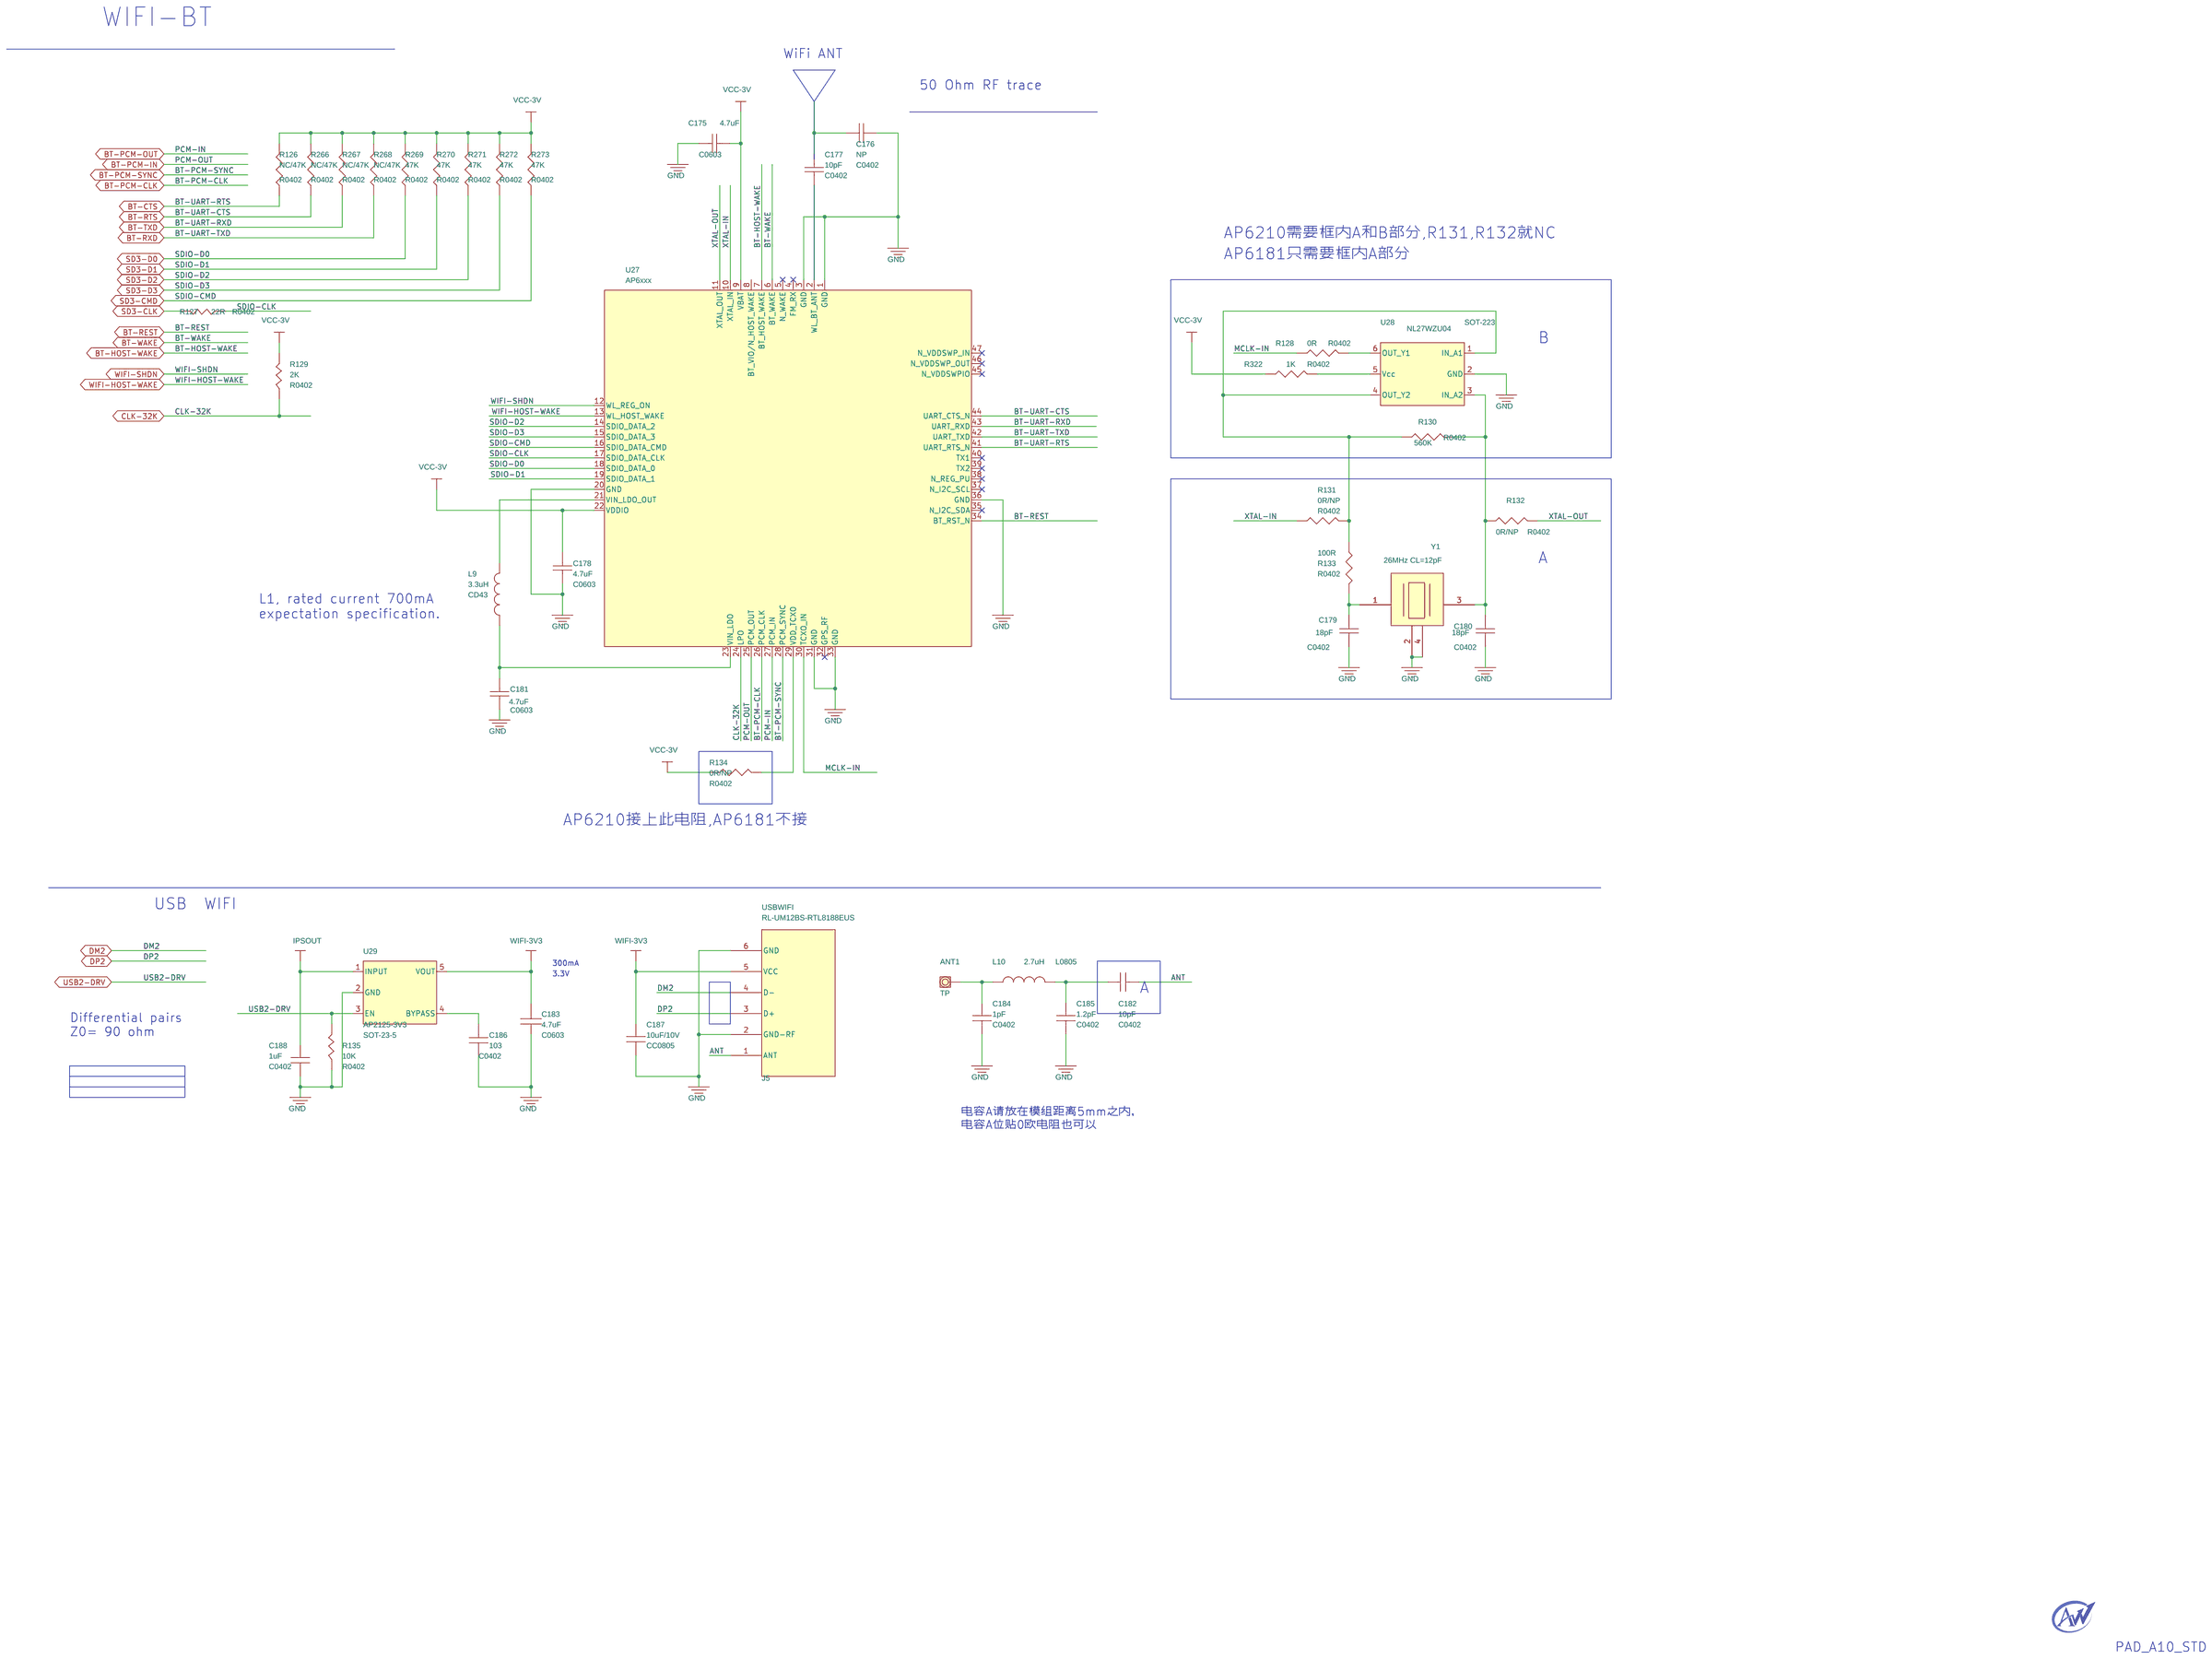
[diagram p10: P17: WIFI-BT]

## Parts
sheet P05: CPU1
U1  FBGA441-A20_42  (sections -1,-2,-3,-4)
sheet P08: DDR3 16bit x 2pcs
R1  240-1%  [R0402]
sheet P10: POWER1
C98  10uF  [CC0805]
C99  10uF  [CC0805]
C100  1uF  [C0402]
C101  1uF  [C0402]
C102  10uF  [CC0805]
C103  1uF  [C0402]
C104  4.7uF  [C0603]
C105  10uF  [CC0805]
C106  1uF  [C0402]
C107  102  [C0402]
C108  4.7uF  [C0603]
C109  4.7uF  [C0603]
C111  10uF  [CC0805]
C112  1uF  [C0402]
C113  10uF  [CC0805]
C114  102  [C0402]
C115  10uF  [CC0805]
C116  10uF  [CC0805]
C117  10uF  [CC0805]
C118  102  [C0402]
C119  4.7uF  [C0603]
C120  4.7uF  [C0603]
C121  4.7uF  [C0603]
C122  10uF  [CC0805]
C123  102  [C0402]
C124  10uF  [CC0805]
D1  1N4148  [DO-35]
D2  NC/POWER  [LED0805]
D3  NC/CHARGING  [LED0805]
J1  ACIN  [POWER-JACK]
J2  CON3  [CON3P254]
L1  2.2uH@1.5A DCR<0.1R  [CD43]
L2  2.2uH@1.5A DCR<0.1R  [CD43]
L3  2.2uH@1.5A DCR<0.1R  [CD43]
Q10  NC/MMBT3904  [SOT-23]
Q11  NC/AO3423  [SOT-23]
R24  47K  [R0402]
R25  2K2  [R0402]
R26  100R  [R0402]
R27  200K/1%  [R0402]
R28  22R  [R0402]
R29  1R  [R0402]
R30  0R03-1%-1/8W  [R0805]
R31  1K  [R0402]
R32  47K  [R0402]
R33  2K  [R0402]
R34  2K  [R0402]
R35  NC/224  [R0402]
R36  NC/224  [R0402]
R37  510R  [R0402]
R38  NC/0R  [R1206]
R39  100K  [R0402]
R40  200K  [R0402]
R226  NC/510K  [R0402]
R227  NC/100K  [R0402]
R230  NC/47K  [R0402]
R318  200K  [R0402]
R319  100K  [R0402]
SW1  PWRON  [SW4_SMD]
SW2  RESET  [SW4_SMD]
U9  AXP209  [QFN48]
sheet P11: POWER2
C125  47pF  [C0402]
C126  47pF  [C0402]
C127  1uF  [C0402]
C128  10uF  [CC0805]
C129  224  [C0402]
C130  10uF  [CC0805]
C131  10uF  [CC0805]
C132  224  [C0402]
C133  10uF  [CC0805]
C134  1uF  [C0402]
C397  10uF  [CC0805]
C398  10uF  [CC0805]
D4  XBS104S14  [SOD123]
L4  2.2uH@1.5A DCR<0.1R  [CD43]
L5  2.2uH@1.5A DCR<0.1R  [CD43]
L6  2.2uH-2A-DCR<0.1R  [CD43]
R41  442K/1%  [R0402]
R42  110K/1%  [R0402]
R43  150K/1%  [R0402]
R44  100K/1%  [R0402]
R45  1k  [R0402]
R46  100K-1%  [R0402]
R47  13K-1%  [R0402]
U10  AP3410\SY8088  [SOT-23-5]
U11  AP3410\SY8088  [SOT-23-5]
U12  SY7152  [SOT-23-6]
sheet P13: HDMI-CSI
C140  4.7uF  [C0603]
C141  103  [C0402]
C142  1uF  [C0402]
CON1  HDMI_TYPE_C  [hdmi_19_0_4mm]
CON2  gt2005  [lcdjack-24]
CON3  gc0308  [lcdjack-24]
R55  47K  [R0402]
R56  2K  [R0402]
R57  2K  [R0402]
R58  22R  [R0402]
R61  22R  [R0402]
R63  22R  [R0402]
R65  22R  [R0402]
R66  100K  [R0402]
R67  100K  [R0402]
R68  100K  [R0402]
R69  100K  [R0402]
R70  10K  [R0402]
RN1  22R*4  [RCA80-8]
RN3  22R*4  [RCA80-8]
TP7  T_POINT_R  [tp_pad]
TP8  T_POINT_R  [tp_pad]
TP9  T_POINT_R  [tp_pad]
TP10  T_POINT_R  [tp_pad]
U17  rRClamp0524P  [RCLAMP0524P]
U18  rRClamp0524P  [RCLAMP0524P]
U19  rRClamp0524P  [RCLAMP0524P]
U20  AP2125  [SOT-23-5]
sheet P16: LCD
C153  104/50V  [C0402]
C154  1uF  [C0402]
C155  224  [C0402]
C156  10uF  [CC0805]
C157  102  [C0402]
C158  10uF  [CC0805]
C159  104/50V  [C0402]
C160  104/50V  [C0402]
C161  1uF  [C0402]
C162  224  [C0402]
C163  104  [C0402]
C164  104  [C0402]
C165  10uF  [CC0805]
C166  102  [C0402]
C167  104  [C0402]
C168  10uF/50V  [CC0805]
C169  104/50V  [C0402]
C170  10uF  [CC0805]
C171  10uF/16V  [CC0805]
C172  104  [C0402]
C173  10uF  [CC0805]
C174  104/16V  [C0402]
C229  1uF  [C0402]
CON4  AT070TN93
CON5  CON  [con12_cm0_5]
CON6  AT070TN93  [lcd_hsd070idw_60p_top]
D6  SS14/IN5819  [SOD-123]
D7  BAT54S  [SOT-23]
D8  15V  [SOD123]
D9  BAT54S  [SOT-23]
D10  6.8V  [SOD123]
D11  SS14/IN5819  [SOD123]
D12  NC/SS24  [SOD-123]
HR1  NC/10K  [R0402]
HR2  NC/10K  [R0402]
HR3  10K  [R0402]
L7  22uH  [CD32]
L8  10uH  [CD32]
LSR1  33K  [R0402]
Q4  AO3423  [SOT-23]
Q5  MMBT3904  [SOT-23]
Q6  AO3423  [SOT-23]
Q7  NC/AO3423  [SOT-23]
R95  20K  [R0402]
R96  510K  [R0402]
R97  51K/1%  [R0402]
R98  1K5  [R0402]
R99  0R  [R0402]
R100  1K/1%  [R0402]
R101  47K  [R0402]
R102  100K  [R0402]
R103  510K  [R0402]
R104  1K5  [R0402]
R105  47K  [R0402]
R106  33R  [R0402]
R107  10K  [R0402]
R108  4.7K  [R0402]
R109  100K  [R0402]
R110  2K7  [R0402]
R111  2R2/1%  [R0402]
R112  4K7  [R0402]
R113  0R/NC  [R0805]
R114  4K7  [R0402]
R115  NC/10K  [R0402]
R116  10K  [R0402]
R117  10K  [R0402]
R118  10K  [R0402]
R119  2K2  [R0402]
R120  NC/1K  [R0402]
R121  10K  [R0402]
R122  NC/10K  [R0402]
R123  2K2  [R0402]
R124  2K2  [R0402]
R125  NC/100K  [R0402]
R187  47K  [R0402]
RN5  100R*4  [RCA80-8]
RN6  100R*4  [RCA80-8]
RN7  100R*4  [RCA80-8]
RN8  100R*4  [RCA80-8]
RN9  100R*4  [RCA80-8]
RN10  100R*4  [RCA80-8]
U25  AP3032  [SOT-23-6]
U26  AP3032\SY7200A  [SOT-23-6]
sheet P17: WIFI-BT
ANT1  TP  [ANT]
C175  4.7uF  [C0603]
C176  NP  [C0402]
C177  10pF  [C0402]
C178  4.7uF  [C0603]
C179  18pF  [C0402]
C180  18pF  [C0402]
C181  4.7uF  [C0603]
C182  10pF  [C0402]
C183  4.7uF  [C0603]
C184  1pF  [C0402]
C185  1.2pF  [C0402]
C186  103  [C0402]
C187  10uF/10V  [CC0805]
C188  1uF  [C0402]
J5  RL-UM12BS-RTL8188EUS  [USBWIFI]
L9  3.3uH  [CD43]
L10  2.7uH  [L0805]
R126  NC/47K  [R0402]
R127  22R  [R0402]
R128  0R  [R0402]
R129  2K  [R0402]
R130  560K  [R0402]
R131  0R/NP  [R0402]
R132  0R/NP  [R0402]
R133  100R  [R0402]
R134  0R/NP  [R0402]
R135  10K  [R0402]
R266  NC/47K  [R0402]
R267  NC/47K  [R0402]
R268  NC/47K  [R0402]
R269  47K  [R0402]
R270  47K  [R0402]
R271  47K  [R0402]
R272  47K  [R0402]
R273  47K  [R0402]
R322  1K  [R0402]
U27  AP6xxx  [GB9664-12X12]
U28  NL27WZU04  [SOT-223]
U29  AP2125-3V3  [SOT-23-5]
Y1  26MHz CL=12pF  [XTAL2.0 X1.6]
sheet P18: USB
C189  10uF  [CC0805]
C190  104  [C0402]
C191  4.7uF  [C0603]
ESD10  ESD-0402-LF  [ESD0402]
ESD11  ESD-0402-LF  [ESD0402]
ESD12  ESD-0402-LF  [ESD0402]
ESD13  ESD-0402-LF  [ESD0402]
J6  USB-MINI-SOCKET  [USB_MINI_AB]
L11  EXC14CE900U / ICMF112P900MFR  [COMMON-FILTERS 4P]
OU1  SY6280  [SOT-23-5]
Q8  MMBT3904  [SOT-23]
R136  10K  [R0402]
R138  510K  [R0402]
R139  13K7-1%  [R0402]
R140  1K  [R0402]
R141  13K7-1%  [R0402]
R143  100K  [R0402]

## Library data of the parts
U1 = A20_0: Color: Default; Location X-Coordinate: 0; Location Y-Coordinate: 0; Power Pins Visible: False; Primitive: DEFAULT; SPLIT_INST: TRUE; SWAP_INFO: (S1+S2+S3+S4)
R1 R24-R29 R31-R37 R39-R47 R66-R69 R126 R136 R138-R141 R143 R226 R227 R266-R273 R318 R319 = R
C98-C109 C111-C113 C115-C117 C119 C120 C122 C124 C128 C130 C131 C133 C397 C398 = CAPACITOR_3: PAGE: 1
C114 C118 C123 C125-C127 C129 C132 = CAPACITOR_1: PAGE: 1
C121 = CAPACITOR_0: PAGE: 1
D1 = 1N4500
D2 D3 = LED_0: PAGE: 1
J1 = BNC-2
J2 = CON3
L1-L6 L9 = INDUCTOR_6
Q5 Q8 Q10 = NPN
Q4 Q6 Q7 Q11 = PMOS
R30 R38 = R: PAGE: 1
HR1-HR3 LSR1 R55-R57 R95-R125 R187 R230 = RESISTOR
SW1 SW2 = SW_PUSH
U9 = AXP209
C134 = CAPACITOR
D4 = DIODE_SCHOTTKY
U10 U11 = RT9293B_0_v2
U12 = RT9266PE_3
C140 C183 = C_20: 1ST PART DESCRIPTION: CAP 2.2uF X7R 16V 20%; Status: Taiwan; Tolerance: Y5V_20%
C141 C142 C186 C188 = C_19
CON1 = HDMI19_TYPE_C
CON2 CON3 = CN_24X1
R58 R61 R63 R65 = RESISTOR_0
R70 R127 R129 R135 = R_0: 1ST PART DESCRIPTION: RESISTOR 6.8 OHM 1/16 5%; Pin Names Rotate: True; Pin Names Visible: False; Pin Numbers Visible: False
RN1 RN3 RN5-RN10 = R-PACK4_1
TP7-TP10 = T_POINT_R
U17-U19 = rRClamp0524P
U20 U29 = LP3985IM5-3_2.3
C153-C161 C163-C169 C171-C174 C229 = CAPACITOR_0: PAGE: 2
C162 = CAPACITOR_1: PAGE: 2
C170 C189-C191 = CAPACITOR_0
CON4 = AT070TN93
CON5 = RT9266PE_1
CON6 = AT070TN93_10
D6 D11 D12 = D_0: Allegro PCB Footprint: d2513A
D7 D9 = DIODE_DUAL
D8 D10 = DIODE_SCHOTTKY_0: RoHS 1.0 Ampere Schottky Barrier Rectifiers  SOD-123
L7 L8 = INDUCTOR: RoHS Power Inductor 22uH 300mA H<1.8MM,CD32
U25 = AP3019_0
U26 = AP3031_0
ANT1 = TEST_0: 1ST PART DESCRIPTION: TESTPOINT
C175-C181 = CAPNP_Dup1_1
C182 C184 C185 = CAP_NP_2: X5R
C187 = CAP_NP_1: X5R
J5 = MINI_USB-B_5
L10 = INDUCTOR_4: C4K-2.5H
R128 R130-R134 R322 = R_0_v2
U27 = AP6493_8: Device: AMPAK_SIP; ORCAD_LIB: MODULE; QVL: AMPAK
U28 = LM1086_2
Y1 = Crystal_0
ESD10-ESD13 = DIODE_TVS_LC_2: RoHS ESD-0603-LF SMT 0402; PN: 450-0001-216; chinese name: ¬ðªi§l¦¬¾¹; ㄑ莱坝: ¤O¼Ý; ³æ¦ì: PCS
J6 = USB_MINI_SOCKET
L11 = R-PACK4_0
OU1 = RT9266PE_2

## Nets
AVCC: C119.1 D1.1(A) U1.T19(AVCC) U9.12(LDO2) U10.1(EN) ; also on sheet 18
VBAT-CH: C112.1 C117.1 L1.1 Q7.3(DRAIN) R30.2 U9.43(CHSENSE)
VCC-5V: C189.2 C398.1 CON1.18(+5V) D4.2 OU1.5(IN) R46.2 R56.1 R57.1
ACIN: C98.2 D12.1 J1.1(CENTER1) Q11.3(DRAIN) R29.2 R38.1 R120.2 R319.2 U9.32(ACIN1) U9.33(ACIN2)
ACIN-EN: R230.2 U1.C5(LCD1_D5/UART4_RX/EINT5/CSI1_D5/PH5)
ACIN-WAKEUP: R318.2 R319.1 U9.19(GPIO0/LDO)
ANT: C182.2 J5.1(ANT)
BAT: C112.2 C116.1 C121.2 J2.1 R30.1 U9.38(BAT1) U9.39(BAT2) U9.42(BATSENSE)
BT-CTS: R126.1 U1.E16(EINT29/SPI1_CLK/UART2_CTS/PI17) U27.41(UART_RTS_N)
BT-HOST-WAKE: U1.E13(HSDA/UART7_RX/PS2_SDA0/PI21) U27.7(BT_HOST_WAKE)
BT-PCM-CLK: U1.A12(I2S_BCLK/AC97_BCLK/PB6) U27.26(PCM_CLK)
BT-PCM-IN: U1.C9(I2S_DI/AC97_DI/SPDIF_DI/PB12) U27.25(PCM_OUT)
BT-PCM-OUT: U1.A11(I2S_DO0/AC97_DO/PB8) U27.27(PCM_IN)
BT-PCM-SYNC: U1.B12(I2S_LRCK/AC97_SYNC/PB7) U27.28(PCM_SYNC)
BT-REST: U1.B13(I2S_MCLK/AC97_MCLK/PB5) U27.34(BT_RST_N)
BT-RTS: R266.1 U1.E17(EINT28/SPI1_CS0/UART2_RTS/PI16) U27.44(UART_CTS_N)
BT-RXD: R268.1 U1.D14(EINT31/SPI1_MISO/UART2_RX/PI19) U27.42(UART_TXD)
BT-TXD: R267.1 U1.E15(EINT30/SPI1_MOSI/UART2_TX/PI18) U27.43(UART_RXD)
BT-WAKE: U1.E14(HSCL/UART7_TX/PS2_SCK0/PI20) U27.6(BT_WAKE)
CAM-F-RESET#: CON3.6 R69.1 U1.B2(LCD1_D14/ETXD3/KP_IN4/SMC_VPPEN/EINT14/CSI1_D14/PH14)
CAM-F-STBY-EN: CON3.8 R68.1 U1.D1(LCD1_D19/ERXERR/KP_OUT1/SMC_SDA/EINT19/CSI1_D19/PH19)
CAM-PWR-EN: R70.1 U1.B1(LCD1_D16/ETXD1/KP_IN6/SMC_DET/EINT16/CSI1_D16/PH16) U20.3(EN)
CAM-R-RESET#: CON2.6 R67.1 U1.A2(LCD1_D13/PS2_SDA1/SMC_RST/EINT13/CSI1_D13/PH13)
CAM-R-STBY-EN: CON2.8 R66.1 U1.C2(LCD1_D18/ERXCK/KP_OUT0/SMC_SLK/EINT18/CSI1_D18/PH18)
CARD-VCC: C125.1 C131.1 C132.1 C142.1 C170.2 C175.2 C178.2 CON5.6(VCC) L5.1 Q6.2(SOURCE) R24.2 R33.2 R34.2 R35.2 R41.1 R126.2 R129.1 R134.1 R136.1 R266.2 R267.2 R268.2 R269.2 R270.2 R271.2 R272.2 R273.2 R322.2 U1.AB19(VCC-HP) U1.H8(VCC0) U1.H9(VCC1) U1.H10(VCC0-PA) U1.H15(VCC2) U1.H19(VCC0-PC) U1.J8(VCC3) U1.J9(VCC4) U1.J10(VCC1-PA) U1.J14(VCC5) U1.J19(VCC1-PC) U1.L15(VCC1-USB) U1.L16(VCC0-USB) U1.N19(VCC-PF) U1.P16(VCC-PLL) U1.T13(VCC-HDMI) U1.W12(VCC0-LVDS) U1.W13(VCC1-LVDS) U1.W14(VCC2-LVDS) U1.W15(VCC33-TVOUT) U1.W16(VCC33-TVIN) U20.1(INPUT) U27.9(VBAT) U27.22(VDDIO) ; also on sheet 12 13 14 15 18
CHGLED: D3.2(CATHODE) U9.36(CHGLED/GPO)
CLK32K-IN: U1.F1(X32KI) ; also on sheet 14
CLK32K-OUT: U1.F2(X32KO) ; also on sheet 14
CLK-32K: R129.2 U1.C16(SPI0_MOSI/UART6_TX/CLK_OUT_A/EINT24/PI12) U27.24(LPO)
CPUVDD: C122.1 C123.1 L3.2 U1.H11(VDD0-CPU) U1.H12(VDD1-CPU) U1.H13(VDD2-CPU) U1.H14(VDD3-CPU) U1.J12(VDD4-CPU) U1.J13(VDD5-CPU) U9.10(DCDC2) ; also on sheet 14
CSI0-D0: RN3.4(R4) U1.C23(TS0_D0/CSI0_D0/PE4)
CSI0-D1: RN3.2(R2) U1.C22(TS0_D1/CSI0_D1/PE5)
CSI0-D2: RN3.1(R1) U1.B23(TS0_D2/CSI0_D2/PE6)
CSI0-D3: RN3.3(R3) U1.B22(TS0_D3/CSI0_D3/PE7)
CSI0-D4: RN1.1(R1) U1.A23(TS0_D4/CSI0_D4/PE8)
CSI0-D5: RN1.2(R2) U1.A22(TS0_D5/CSI0_D5/PE9)
CSI0-D6: RN1.3(R3) U1.B21(TS0_D6/CSI0_D6/PE10)
CSI0-D7: RN1.4(R4) U1.A21(TS0_D7/CSI0_D7/PE11)
CSI0-HSYNC: R61.2 U1.D23(TS0_SYNC/CSI0_HSYNC/PE2)
CSI0-MCLK: R63.2 U1.E22(TS0_ERR/CSI0_MCLK/PE1)
CSI0-PCLK: R65.2 U1.E23(TS0_CLK/CSI0_PCLK/PE0)
CSI0-VSYNC: R58.2 U1.D22(TS0_DVLD/CSI0_VSYNC/PE3)
CSI1-D0: CON3.19 U1.D20(TS1_D0/CSI1_D0/SDC1_D2/CSI0_D8/PG4)
CSI1-D1: CON3.21 U1.C21(TS1_D1/CSI1_D1/SDC1_D3/CSI0_D9/PG5)
CSI1-D2: CON3.22 U1.E19(TS1_D2/CSI1_D2/UART3_TX/CSI0_D10/PG6)
CSI1-D3: CON3.20 U1.C20(TS1_D3/CSI1_D3/UART3_RX/CSI0_D11/PG7)
CSI1-D4: CON3.18 U1.D19(TS1_D4/CSI1_D4/UART3_RTS/CSI0_D12/PG8)
CSI1-D5: CON3.16 U1.C19(TS1_D5/CSI1_D5/UART3_CTS/CSI0_D13/PG9)
CSI1-D6: CON3.14 U1.D18(TS1_D6/CSI1_D6/UART4_TX/CSI0_D14/PG10)
CSI1-D7: CON3.12 U1.C18(TS1_D7/CSI1_D7/UART4_RX/CSI0_D15/PG11)
CSI1-HSYNC: CON3.9 TP8.1(TP) U1.E20(TS1_SYNC/CSI1_HSYNC/SDC1_D0/PG2)
CSI1-MCLK: CON3.13 TP10.1(TP) U1.E21(TS1_ERR/CSI1_MLCK/SDC1_CLK/PG1)
CSI1-PCLK: CON3.17 TP9.1(TP) U1.F20(TS1_CLK/CSI1_PCLK/SDC1_CMD/PG0)
CSI1-VSYNC: CON3.7 TP7.1(TP) U1.D21(TS1_DVLD/CSI1_VSYNC/SDC1_D1/PG3)
CSI-AVDD: C120.1 CON2.4 CON3.4 U9.11(LDO4)
CSI-DVDD: C140.2 CON2.10 CON3.10 U20.5(VOUT)
CSI-IOVDD: C109.2 CON2.11 CON3.11 R66.2 R67.2 R68.2 R69.2 U1.E18(VCC-PG) U1.F19(VCC-PE) U9.41(LDO3) ; also on sheet 14
DITHB: CON4.47(DITHB) HR2.1 R117.2
DLLVDD: C113.1 C114.1 L2.2 U1.J15(VDD0-SYS) U1.J16(VDD1-SYS) U1.K9(VDD2-SYS) U1.K10(VDD3-SYS) U1.K15(VDD4-SYS) U1.K16(VDD-USB) U1.L8(VDD5-SYS) U1.L9(VDD6-SYS) U1.M8(VDD0-DLL) U1.M15(VDD12-0-SATA) U1.M16(VDD12-1-SATA) U1.N9(VDD1-DLL) U1.P9(VDD2-DLL) U1.R9(VDD7-SYS) U1.R10(VDD8-SYS) U1.T8(VDD9-SYS) U9.17(DCDC3) ; also on sheet 14
DM0: L11.1(R1) U1.N20(DM0)
DM2: J5.4(D-) U1.R20(DM2)
DP0: L11.2(R2) U1.N21(DP0)
DP2: J5.3(D+) U1.R21(DP2)
DRAM-VCC: C98.1 C99.1 C100.1 C101.2 C102.1 C103.2 C104.2 C105.1 C106.2 C107.1 C108.1 C109.1 C111.2 C113.2 C114.2 C115.2 C116.2 C117.2 C118.2 C119.2 C120.2 C121.1 C122.2 C123.2 C124.2 C126.1 C127.2 C128.1 C128.2 C129.1 C129.2 C130.2 C131.2 C132.2 C133.2 C134.1 C140.1 C141.1 C142.2 C153.1 C156.1 C157.1 C158.1 C159.1 C160.1 C161.1 C163.1 C164.1 C165.1 C166.1 C167.1 C168.1 C169.1 C170.1 C171.1 C172.1 C173.1 C174.1 C175.1 C176.2 C178.1 C179.1 C180.1 C181.1 C183.1 C184.2 C185.2 C186.1 C187.2 C188.2 C189.1 C190.1 C191.1 C229.1 C397.2 C398.2 CON1.1(DATA2_GND) CON1.4(DATA1_GND) CON1.7(DATA0_GND) CON1.10(CLOCK_GND) CON1.13(DDC/CEC_GND) CON1.20(SHIELD1) CON1.21(SHIELD2) CON1.22(SHIELD3) CON1.23(SHIELD4) CON2.2 CON2.15 CON3.2 CON3.15 CON4.5(GND0) CON4.36(GND1) CON4.38(GND2) CON4.48(GND3) CON5.1(GND) CON5.7(GND0) CON5.12(GND1) CON6.1(AGND0) CON6.4(GND0) CON6.7(GND1) CON6.15(GND2) CON6.17(GND3) CON6.20(GND4) CON6.23(GND5) CON6.26(GND6) CON6.29(GND7) CON6.32(GND8) CON6.33(GND_LVDS) CON6.39(AGND1) CON6.43(GND9) CON6.45(GND10) CON6.53(GND11) CON6.55(GND12) CON6.59(GND13) CON6.61(GND15) CON6.62(GND14) D2.2(CATHODE) D8.1 D9.2 D10.2 ESD10.2 ESD11.2 ESD12.2 ESD13.2 HR2.2 HR3.2 J1.2(CENTER2) J2.3 J5.2(GND-RF) J5.6(GND) J6.5(GND) J6.6(SHIELD1) J6.7(SHIELD2) J6.8(SHIELD3) J6.9(SHIELD4) L4.1 OU1.2(GND) Q5.2(E) Q8.2(E) Q10.2(E) R1.2 R25.2 R26.2 R27.2 R37.1 R40.1 R42.2 R43.1 R44.2 R47.1 R55.2 R70.2 R95.1 R100.1 R101.1 R103.2 R105.2 R108.2 R109.1 R111.1 R121.2 R122.2 R123.2 R124.2 R125.1 R135.2 R138.1 R139.1 R227.1 R318.1 SW1.1 SW1.2 U1.AA1(SDQ8) U1.AA3(SA8) U1.AA5(ODT) U1.AA6(SRST) U1.AA8(SVREF3) U1.AA17(TVIN2) U1.AA18(GND25-TVIN) U1.AB2(SDQ11) U1.AB3(SDQ14) U1.AB4(SDQ6) U1.AB5(SDQ3) U1.AB6(SDQS0) U1.AB18(TVIN1) U1.AC2(SDQ12) U1.AC3(SDQ7) U1.AC4(SDQ1) U1.AC7(SDQ0) U1.AC8(SDQ2) U1.AC18(TVIN0) U1.C13(ETXERR/CAN_RX/UART1_RING/I2S1_DI/PA17) U1.D5(RXD3/SPI1_CS0/UART2_RTS/PA0) U1.D6(RXD1/SPI1_MOSI/UART2_TX/PA2) U1.D7(TXD3/SPI1_CS1/PA4) U1.D10(ERXDV/GRXCTL/UART1_TX/PA10) U1.D11(MDIO/UART6_TX/UART1_RTS/PA12) U1.D12(ETXCK/UART7_TX/UART1_DTR/I2S1_BCLK/PA14) U1.D13(ECOL/GCLKIN/CAN_TX/UART1_DCD/I2S1_DO/PA16) U1.E5(RXD2/SPI1_CLK/UART2_CTS/PA1) U1.E6(RXD0/SPI1_MISO/UART2_RX/PA3) U1.E9(ERXERR/SPI3_CS1/I2S1_MCLK/PA9) U1.E10(MDC/UART1_RX/PA11) U1.E11(ETXEN/GTXCTL/UART6_RX/UART1_CTS/PA13) U1.E12(ECRS/GTXCK/UART7_RX/UART1_DSR/I2S1_LRCK/PA15) U1.G3(GND0) U1.G4(GND1) U1.G5(VCC0-DRAM) U1.H2(SDQ31) U1.H3(SVREF0) U1.H4(SVREF1) U1.H5(VCC1-DRAM) U1.H16(TEST) U1.J1(SDQ24) U1.J5(GND2) U1.J11(GND13) U1.K1(SDQS3) U1.K2(SDQ27) U1.K3(SBA0) U1.K4(SBA2) U1.K5(GND3) U1.K11(GND14) U1.K12(GND15) U1.K13(GND16) U1.K14(GND35) U1.L4(SBA1) U1.L5(VCC2-DRAM) U1.L10(GND17) U1.L11(GND18) U1.L12(GND19) U1.L13(GND36) U1.L14(GND37) U1.M1(SDQ30) U1.M2(SDQ23) U1.M3(SA7) U1.M4(SA3) U1.M5(VCC3-DRAM) U1.M9(GND10) U1.M10(GND20) U1.M11(GND21) U1.M12(GND22) U1.M13(GND23) U1.M14(GND38) U1.N1(SDQ22) U1.N2(SDQ17) U1.N3(SCKE) U1.N4(SA5) U1.N5(GND4) U1.N10(GND11) U1.N11(GND24) U1.N12(GND25) U1.N13(GND39) U1.N14(GND40) U1.N15(VDD25-0-SATA) U1.N16(VDD25-1-SATA) U1.P1(SDQ19) U1.P4(SA9) U1.P5(GND5) U1.P10(GND12) U1.P11(GND26) U1.P12(GND27) U1.P13(GND43) U1.P14(GND42) U1.P15(PLLGND) U1.R1(SDQS2) U1.R2(SDQM2) U1.R5(VCC4-DRAM) U1.R11(GND28) U1.R12(GND29) U1.R13(GND41) U1.T2(SDQ16) U1.T3(SWE) U1.T4(SRAS) U1.T5(VCC5-DRAM) U1.T9(VDDQE) U1.T11(GND30) U1.T12(GND31) U1.U4(SA2) U1.U5(GND6) U1.U19(AGND) U1.V3(SCS0) U1.V4(SA6) U1.V5(GND7) U1.V19(HPGND) U1.W2(SDQ13) U1.W5(VCC6-DRAM) U1.W6(VCC7-DRAM) U1.W7(VCC8-DRAM) U1.W9(GND32) U1.W10(GND33) U1.W11(GND34) U1.W17(VDD25-TVIN) U1.W18(GND44) U1.Y1(SDQ10) U1.Y2(SDQ15) U1.Y4(SA4) U1.Y5(SVREF2) U1.Y6(VCC9-DRAM) U1.Y7(GND8) U1.Y8(GND9) U1.Y17(TVIN3) U1.Y18(GND33-TVIN) U9.9(PGND2) U9.16(PGND3) U9.22(AGND) U9.46(PGND1) U9.49(THERMAL) U10.2(GND) U11.2(GND) U12.2(GND) U17.3(GND1) U17.8(GND2) U18.3(GND1) U18.8(GND2) U19.3(GND1) U19.8(GND2) U20.2(GND) U25.2(GND) U26.2(GND) U27.1(GND) U27.3(GND) U27.20(GND) U27.31(GND) U27.33(GND) U27.36(GND) U28.2(GND) U29.2(GND) Y1.2 Y1.4 ; also on sheet 12 13 14 15 17 18 19
EXTEN: R45.1 U9.20(EXTEN) U12.4(EN)
HCEC: CON1.14(CEC) U1.P23(CEC_HDMI) U19.1(IN1) U19.10(OUT1)
HHPD: CON1.19(HOT_PLUG_DET) R55.1 U1.P22(HPD_HDMI) U19.5(IN4) U19.6(OUT4)
HPBP: U1.AC19(HPBP) ; also on sheet 14
HPCOM: U1.AA19(HPCOM) ; also on sheet 15
HPCOMFB: U1.AA20(HPCOMFB) ; also on sheet 15
HPL: U1.Y19(HPOUTL) ; also on sheet 15
HPR: U1.W19(HPOUTR) ; also on sheet 15
HSCL: CON1.15(SCL) R56.2 U1.R23(SCL_HDMI) U19.2(IN2) U19.9(OUT2)
HSDA: CON1.16(SDA) R57.2 U1.R22(SDA_HDMI) U19.4(IN3) U19.7(OUT3)
HTX0N: CON1.9(DATA0-) U1.V22(TX0N_HDMI) U18.2(IN2) U18.9(OUT2)
HTX0P: CON1.8(DATA0+) U1.V23(TX0P_HDMI) U18.1(IN1) U18.10(OUT1)
HTX1N: CON1.6(DATA1-) U1.U22(TX1N_HDMI) U17.5(IN4) U17.6(OUT4)
HTX1P: CON1.5(DATA1+) U1.U23(TX1P_HDMI) U17.4(IN3) U17.7(OUT3)
HTX2N: CON1.3(DATA2-) U1.T22(TX2N_HDMI) U17.2(IN2) U17.9(OUT2)
HTX2P: CON1.2(DATA2+) U1.T23(TX2P_HDMI) U17.1(IN1) U17.10(OUT1)
HTXCN: CON1.12(CLOCK-) U1.W22(TXCN_HDMI) U18.5(IN4) U18.6(OUT4)
HTXCP: CON1.11(CLOCK+) U1.W23(TXCP_HDMI) U18.4(IN3) U18.7(OUT3)
IPSOUT: C102.2 C105.2 C108.2 C115.1 C124.1 C130.1 C133.1 C134.2 C188.1 C397.1 L6.1 R28.1 R36.2 R113.2 SW2.1 U9.7(VIN2) U9.13(LDO24IN) U9.14(VIN3) U9.34(PS1) U9.35(PS2) U9.40(LDO3IN) U9.44(VIN1) U10.4(IN) U11.4(IN) U12.5(IN) U29.1(INPUT) ; also on sheet 15
IR-RX: U1.A13(IR0_RX/PB4) ; also on sheet 18
JTAG-CK: U1.B10(JTAG_CK0/SPI2_CLK/PB15) ; also on sheet 13
JTAG-DI: U1.B9(JTAG_DI0/SPI2_MISO/PB17) ; also on sheet 13
JTAG-DO: U1.A9(JTAG_DO0/SPI2_MOSI/PB16) ; also on sheet 13
JTAG-MS: U1.A10(JTAG_MS0/SPI2_CS0/PB14) ; also on sheet 13
JTAG-SEL: U1.T10(JTAG_SEL) ; also on sheet 13
L/R: CON4.39(L/R) R115.2 R121.1
LCD0-CLK: R106.1 U1.Y9(LCD0_CLK/SMC_VCCEN/PD24)
LCD0-D0: CON6.30(PIND0) RN6.1(R1) U1.AB15(LCD0_D0/LVDS0_VP0/PD0)
LCD0-D1: CON6.31(NIND0) RN6.2(R2) U1.AC15(LCD0_D1/LVDS0_VN0/PD1)
LCD0-D2: CON6.27(PIND1) RN6.3(R3) U1.AB14(LCD0_D2/LVDS0_VP1/PD2)
LCD0-D3: CON6.28(NIND1) RN6.4(R4) U1.AC14(LCD0_D3/LVDS0_VN1/PD3)
LCD0-D4: CON6.24(PIND2) RN5.1(R1) U1.AB13(LCD0_D4/LVDS0_VP2/PD4)
LCD0-D5: CON6.25(NIND2) RN5.2(R2) U1.AC13(LCD0_D5/LVDS0_VN2/PD5)
LCD0-D6: CON6.21(PINC) RN5.3(R3) U1.AB12(LCD0_D6/LVDS0_VPC/PD6)
LCD0-D7: CON6.22(NINC) RN5.4(R4) U1.AC12(LCD0_D7/LVDS0_VNC/PD7)
LCD0-D8: CON6.18(PIND3) RN8.1(R1) U1.AB11(LCD0_D8/LVDS0_VP3/PD8)
LCD0-D9: CON6.19(NIND3) RN8.2(R2) U1.AC11(LCD0_D9/LVDS0_VN3/PD9)
LCD0-D10: RN8.3(R3) U1.Y15(LCD0_D10/LVDS1_VP0/PD10)
LCD0-D11: RN8.4(R4) U1.AA15(LCD0_D11/LVDS1_VN0/PD11)
LCD0-D12: RN7.1(R1) U1.Y14(LCD0_D12/LVDS1_VP1/PD12)
LCD0-D13: RN7.2(R2) U1.AA14(LCD0_D13/LVDS1_VN1/PD13)
LCD0-D14: RN7.3(R3) U1.Y13(LCD0_D14/LVDS1_VP2/PD14)
LCD0-D15: RN7.4(R4) U1.AA13(LCD0_D15/LVDS1_VN2/PD15)
LCD0-D16: RN10.1(R1) U1.Y12(LCD0_D16/LVDS1_VPC/PD16)
LCD0-D17: RN10.2(R2) U1.AA12(LCD0_D17/LVDS1_VNC/PD17)
LCD0-D18: RN10.3(R3) U1.Y11(LCD0_D18/LVDS1_VP3/PD18)
LCD0-D19: RN10.4(R4) U1.AA11(LCD0_D19/LVDS1_VN3/PD19)
LCD0-D20: RN9.1(R1) U1.Y10(LCD0_D20/CSI1_MCLK/PD20)
LCD0-D21: RN9.2(R2) U1.AA10(LCD0_D21/SMC_VPPEN/PD21)
LCD0-D22: RN9.3(R3) U1.AB10(LCD0_D22/SMC_VPPPP/PD22)
LCD0-D23: RN9.4(R4) U1.AC10(LCD0_D23/SMC_DET/PD23)
LCD0-DE: CON4.9(DE) U1.AA9(LCD0_DE/SMC_RST/PD25)
LCD0-HSYNC: CON4.11(HS) U1.AB9(LCD0_HSYNC/SMC_SLK/PD26)
LCD0-VSYNC: CON4.10(VS) U1.AC9(LCD0_VSYNC/SMC_SDA/PD27)
LCD-AVDD: C153.2 C158.2 CON4.43(AVDD) D6.2 D7.1 R95.2 R97.2 R118.1 R119.1 U25.5(OVR)
LCD-BL-EN: R187.2 U1.B4(LCD1_D7/UART5_RX/MS_CLK/EINT7/CSI1_D7_/PH7)
LCD-CSX: U1.E7(TXD2/SPI3_CS0/PA5)
LCD-CTL: C154.1 Q4.1(GATE) Q5.3(C) Q6.1(GATE) R96.2
LCD-POWER: C154.2 C165.2 C166.2 D12.2 L8.1 Q4.2(SOURCE) Q7.2(SOURCE) R96.1 R113.1 U26.6(VDD)
LCD-PWR: R102.2 U1.C4(LCD1_D8/ERXD3/KP_IN0/MS_D0/EINT8/CSI1_D8/PH8)
LCD-RESET#: C167.2 CON4.44(RESET) R107.2
LCD-RST: U1.C6(LCD1_D2/UART3_RTS/EINT2/CSI1_D2/PH2)
LCD-RST-P: U1.A4(LCD1_D6/UART5_TX/MS_BS/EINT6/CSI1_D6/PH6)
LCD-SCK: U1.D8(TXD1/SPI3_CLK/PA6)
LCD-SDI: U1.E8(TXD0/SPI3_MOSI/PA7)
LCD-SDO: U1.D9(RXCK/SPI3_MISO/PA8)
LCD-SHUT: U1.B3(LCD1_D11/ERXD0/KP_IN3/MS_D3/EINT11/CSI1_D11/PH11)
LCD-VCC: C171.2 C172.2 CON4.7(DVDD) HR1.1 Q6.3(DRAIN) R107.1 R108.1 R112.1 R115.1 R116.1 R117.1
LDO1SET: R25.1 U9.27(LDO1SET)
LRADC0: U1.AB23(LRADC0) ; also on sheet 14 18
MCLK-IN: R128.2 U27.30(TCXO_IN)
MICIN1: U1.AC20(MICIN1) ; also on sheet 15
MODE: CON4.8(MODE) HR1.2 HR3.1
MT-C: U1.B14(IR0_TX/SPDIF_MCLK/STANBYWFI/PB3) ; also on sheet 18
NALE: U1.M22(NALE/SPI0_MISO/PC1) ; also on sheet 12
NCE0#: U1.K23(NCE0/PC4) ; also on sheet 12
NCE1#: U1.L22(NCE1/PC3) ; also on sheet 12
NCE2#: U1.F23(NCE2/PC17) ; also on sheet 12
NCE3#: U1.F22(NCE3/PC18) ; also on sheet 12
NCLE: U1.L23(NCLE/SPI0_CLK/PC2) ; also on sheet 12
ND0: U1.H23(NDQ0/SDC2_D0/PC8) ; also on sheet 12
ND1: U1.H22(NDQ1/SDC2_D1/PC9) ; also on sheet 12
ND2: U1.G23(NDQ2/SDC2_D2/PC10) ; also on sheet 12
ND3: U1.G22(NDQ3/SDC2_D3/PC11) ; also on sheet 12
ND4: U1.H21(NDQ4/PC12) ; also on sheet 12
ND5: U1.H20(NDQ5/PC13) ; also on sheet 12
ND6: U1.G21(NDQ6/PC14) ; also on sheet 12
ND7: U1.G20(NDQ7/PC15) ; also on sheet 12
NDQS: U1.F21(NDQS/PC24) ; also on sheet 12
NMI#: R32.2 U1.F5(NMI#) U9.5(GPIO2) U9.48(IRQ)
NRB0#: U1.J23(NRB0/SDC2_CMD/PC6) ; also on sheet 12
NRB1#: U1.J22(NRB1/SDC2_CLK/PC7) ; also on sheet 12
NRE#: U1.K22(NRE#/PC5) ; also on sheet 12
NWE#: U1.M23(NWE#/SPI0_MOSI/PC0) ; also on sheet 12
OSC24MI: U1.N23(X24MI) ; also on sheet 14
OSC24MO: U1.N22(X24MO) ; also on sheet 14
PA-SHDN#: U1.A1(LCD1_D15/ETXD2/KP_IN5/SMC_VPPPP/EINT15/CSI1_D15/PH15) ; also on sheet 15
PMU-SCK: R34.1 U1.A15(TWI0_SCK/PB0) U9.2(SCK)
PMU-SDA: R33.1 U1.B15(TWI0_SDA/PB1) U9.1(SDA)
PWM0: R112.2 R114.1 U1.A14(PWM0/PB2)
PWM1: U1.B19(PWM1/TWI4_SDA/PI3)
RESET#: C103.1 R24.1 U1.C14(RESET#) U9.25(PWROK) ; also on sheet 14
RTCVDD: C100.2 U1.K8(VDD-RTC) U9.28(LDO1) ; also on sheet 14
SA0: U1.AC5(SDQS0#) U1.J2(SDQS3#) U1.P2(SDQS2#) U1.U3(SCAS) U1.W1(SDQM1) U1.W4(SA0) U1.Y3(SA13) ; also on sheet 17 19
SA1: U1.AA2(SDQS1#) U1.AB8(SDQ5) U1.AC6(SDQM0) U1.G1(SDQM3) U1.L3(SA10) U1.R4(SA1) U1.U2(SDQ18) ; also on sheet 17 19
SA11: U1.AA4(SA15) U1.W3(SA11) ; also on sheet 17 19
SA12: U1.P3(SA12) U1.R3(SA14) ; also on sheet 17 19
SCKN: U1.V2(SCK#) ; also on sheet 17 19
SCKP: U1.V1(SCK) ; also on sheet 17 19
SD0-CLK: U1.L20(SDC0_CLK/UART0_TX/PF2) ; also on sheet 13
SD0-CMD: U1.L19(SDC0_CMD/JTAG_DO1/PF3) ; also on sheet 13
SD0-D0: U1.M19(SDC0_D0/JTAG_DI1/PF1) ; also on sheet 13
SD0-D1: U1.M20(SDC0_D1/JTAG_MS1/PF0) ; also on sheet 13
SD0-D2: U1.K19(SDC0_D2/JTAG_CK1/PF5) ; also on sheet 13
SD0-D3: U1.K20(SDC0_D3/UART0_RX/PF4) ; also on sheet 13
SD0-DET: U1.B6(LCD1_D1/UART3_RX/EINT1/CSI1_D1/PH1) ; also on sheet 13
SD3-CLK: R127.1 U1.B18(SDC3_CLK/PI5)
SD3-CMD: R273.1 U1.A18(SDC3_CMD/PI4) U27.16(SDIO_DATA_CMD)
SD3-D0: R269.1 U1.A17(SDC3_D0/PI6) U27.18(SDIO_DATA_0)
SD3-D1: R270.1 U1.B17(SDC3_D1/PI7) U27.19(SDIO_DATA_1)
SD3-D2: R271.1 U1.A16(SDC3_D2/PI8) U27.14(SDIO_DATA_2)
SD3-D3: R272.1 U1.B16(SDC3_D3/PI9) U27.15(SDIO_DATA_3)
SDIO-CLK: R127.2 U27.17(SDIO_DATA_CLK)
SDQ20: U1.AB1(SDQS1) U1.AB7(SDQ4) U1.G2(SDQ29) U1.T1(SDQ20) ; also on sheet 17
SDQ21: U1.U1(SDQ21) ; also on sheet 17
SDQ25: U1.L1(SDQ25) ; also on sheet 17
SDQ26: U1.H1(SDQ26) ; also on sheet 17
SDQ28: U1.AC1(SDQ9) U1.L2(SDQ28) ; also on sheet 17
TP-INT: CON5.2(INT) U1.D3(LCD1_D21/EMDC/CAN_RX/EINT21/CSI1_D21/PH21)
TP-WAKEUP: CON5.3(RST) U1.B11(SPI2_CS1/SPDIF_DO/PB13)
TVOUT0: U1.AC16(TVOUT0) ; also on sheet 18
TVOUT1: U1.AB16(TVOUT1) ; also on sheet 18
TVOUT2: U1.AC17(TVOUT2) ; also on sheet 18
TWI1-SCK: CON2.5 CON3.5 U1.A8(TWI1_SCK/PB18) ; also on sheet 13 14
TWI1-SDA: CON2.3 CON3.3 U1.B8(TWI1_SDA/PB19) ; also on sheet 13 14
TWI2-SCK: CON5.4(SCL) U1.C8(TWI2_SCK/PB20) ; also on sheet 14
TWI2-SDA: CON5.5(SDA) U1.C7(TWI2_SDA/PB21) ; also on sheet 14
U/D: CON4.40(U/D) R116.2 R122.1
UART0-RX: U1.B7(UART0_RX/IR1_RX/PB23) ; also on sheet 13
UART0-TX: U1.A7(UART0_TX/IR1_TX/PB22) ; also on sheet 13
UBOOT: U1.W8(UBOOT_SEL) ; also on sheet 18
USB0-DRV: OU1.4(EN) R138.2 U1.C12(I2S_DO1/PB9) U9.6(N_VBUSEN)
USB0-IDDET: ESD13.1 R140.2 U1.B5(LCD1_D4/UART4_TX/EINT4/CSI1_D4/PH4)
USB2-DRV: R135.1 U1.A5(LCD1_D3/UART3_CTS/EINT3/CSI1_D3/PH3) U29.3(EN)
USB-ICTRL: R143.2 U1.A6(LCD1_D0/UART3_TX/EINT0/CSI1_D0/PH0)
USB-WAKEUP: R39.1 R40.2 U9.18(GPIO1)
USBVBUS: C99.2 C190.2 C191.2 ESD10.1 J6.1(VBUS) OU1.1(OUT) Q11.2(SOURCE) R38.2 R39.2 R226.2 U9.31(VBUS)
VCOM: C174.2 CON4.6(VCOM0) CON4.46(VCOM1) R118.2 R119.2 R123.1 R124.1
VGH: C160.2 CON4.41(VGH) D8.2 R98.1 R101.2
VGL: C164.2 CON4.42(VGL) D10.1 R104.2 R105.1
VLED+: C168.2 C169.2 CON4.1(VLED0+) CON4.2(VLED1+) D11.2 U26.5(OVP)
VLED-: CON4.3(VLED0-) CON4.4(VLED1-) R110.2 R111.2
VMIC: U1.AA21(VMIC) ; also on sheet 15
VRA1: U1.W20(VRA1) ; also on sheet 14
VRA2: U1.V20(VRA2) ; also on sheet 14
VRP: U1.W21(VRP) ; also on sheet 14
WIFI-3V3: C183.2 C187.1 J5.5(VCC) U29.5(VOUT)
WIFI-HOST-WAKE: U1.A3(LCD1_D10/ERXD1/KP_IN2/MS_D2/EINT10/CSI1_D10/PH10) U27.13(WL_HOST_WAKE)
WIFI-SHDN: U1.D4(LCD1_D9/ERXD2/KP_IN1/MS_D1/EINT9/CSI1_D9/PH9) U27.12(WL_REG_ON)
XTAL-IN: R131.2 U27.10(XTAL_IN)
XTAL-OUT: R132.1 U27.11(XTAL_OUT)
N31589086: C101.1 U9.26(VINT)
N31589098: C104.1 C107.2 R28.2 U9.21(APS)
N31589141: L2.1 U9.15(LX3)
N31589158: L1.2 U9.45(LX1)
N31589329: D1.2(K) R32.1
N31589444: R26.1 U9.37(TS)
N31589623: C118.1 R31.1 U9.47(PWRON)
N31589693: R27.1 U9.23(BIAS)
N31589718: C106.1 U9.24(VREF)
N31590080: R37.2 SW2.3 U9.4(N_OE)
N31590251: L3.1 U9.8(LX2)
N31710003: C125.2 R41.2 R42.1 U11.5(FB)
N31710066: L5.2 U11.3(LX)
N36249342: R46.1 R47.2 U12.3(FB)
N36249350: D4.1 L6.2 U12.1(LX)
N36921676: C162.1 D9.3
N36921681: CON4.34(R1) RN10.7(R7)
N36921687: CON4.22(G5) RN7.7(R7)
N36921716: C173.2 LSR1.1 R114.2
N36921926: C159.2 D7.2 R98.2
N36921936: CON4.33(R2) RN10.6(R6)
N36921940: CON4.23(G4) RN7.8(R8)
N36921957: CON4.32(R3) RN10.5(R5)
N36921961: CON4.24(G3) RN8.5(R5)
N36922036: CON4.12(B7) RN5.5(R5)
N36922048: CON4.31(R4) RN9.8(R8)
N36922052: CON4.25(G2) RN8.6(R6)
N36922056: CON4.13(B6) RN5.6(R6)
N36922062: CON4.30(R5) RN9.7(R7)
N36922068: CON4.14(B5) RN5.7(R7)
N36922080: CON4.29(R6) RN9.6(R6)
N36922088: CON4.15(B4) RN5.8(R8)
N36922098: CON4.28(R7) RN9.5(R5)
N36922109: CON4.16(B3) RN6.5(R5)
N36922210: CON4.27(G0) RN8.8(R8)
N36922218: CON4.17(B2) RN6.6(R6)
N36922290: R99.1 U25.3(FB)
N36922303: D11.1 L8.2 U26.1(LX)
N36922424: C155.2 C162.2 D6.1 L7.2 U25.1(LX)
N36922442: LSR1.2 R110.1 U26.3(FB)
N36922459: C156.2 C157.2 L7.1 Q4.3(DRAIN) U25.4(EN) U25.6(VDD)
N36922495: C161.2 Q5.1(B) R102.1 R103.1
N36922542: CON4.26(G1) RN8.7(R7)
N36922586: CON4.20(G7) RN7.5(R5)
N36922599: C229.2 R109.2 R187.1 U26.4(EN)
N36922737: CON4.18(B1) RN6.7(R7)
N36923829: CON4.35(R0) RN10.8(R8)
N36923833: CON4.21(G6) RN7.6(R6)
N36923847: CON4.19(B0) RN6.8(R8)
N37237737: R31.2 SW1.3 SW1.4(6)
N37510416: CON4.37(DCLK) R106.2
N37838901: C126.2 R43.2 R44.1 U10.5(FB)
N37838952: L4.2 U10.3(LX)
N40903649: C163.2 D9.1 R104.1
N41025819: R97.1 R99.2 R100.2
N44836958: J6.4(ID) R136.2 R140.1
N44837032: ESD11.1 J6.3(D+) L11.4(R4)
N44837053: ESD12.1 J6.2(D-) L11.3(R3)
N47910881: CON2.19 RN3.5(R5)
N47910887: CON2.20 RN3.6(R6)
N47910891: CON2.21 RN3.7(R7)
N47910904: CON2.17 R65.1
N47910967: CON2.22 RN3.8(R8)
N47910971: CON2.12 RN1.5(R5)
N47910980: CON2.14 RN1.6(R6)
N47910994: CON2.16 RN1.7(R7)
N47910997: CON2.18 RN1.8(R8)
N47911117: CON2.13 R63.1
N47911215: CON2.7 R58.1
N47911218: CON2.9 R61.1
N54665228: C127.1 R45.2 U11.1(EN)
N56909927: C111.1 R29.1
N60281598: C141.2 U20.4(BYPASS)
N61364973: Q7.1(GATE) R120.1 R125.2
N62886813: ANT1.1(A) C184.1 L10.1
N62887074: C182.1 C185.1 L10.2
N62951316: Q8.1(B) R143.1
N62951323: Q8.3(C) R141.1
N62951340: OU1.3(ISET) R139.2 R141.2
N63002686: C186.2 U29.4(BYPASS)
N63027924: R134.2 U27.29(VDD_TCXO)
N63028021: C181.2 L9.1 U27.23(VIN_LDO)
N63028040: C176.1 C177.2
N63028042: C177.1 U27.2(WL_BT_ANT)
N63028760: R130.2 R131.1 R133.2 U28.1(IN_A1) U28.4(OUT_Y2)
N63028774: C180.2 R130.1 R132.2 U28.3(IN_A2) Y1.3
N63028805: R128.1 U28.6(OUT_Y1)
N63028807: R322.1 U28.5(Vcc)
N63028821: C179.2 R133.1 Y1.1
N63143528: R1.1 U1.AA7(SZQ)
N63211171: Q10.3(C) Q11.1(GATE) R226.1
N63655019: L9.2 U27.21(VIN_LDO_OUT)
N63723655: C155.1 D7.3
N63733310: Q10.1(B) R227.2 R230.1
N63733312: D2.1(ANODE) R35.1
N63733313: D3.1(ANODE) R36.1

Not connected (* = marked no-connect by the designer): CON1 17(NC)*; CON2 1* 23* 24*; CON3 1* 23* 24*; CON4 45(NC0)* 49(NC1)* 50(NC2)*; CON5 8(YU)* 9(XL)* 10(YD)* 11(XR)*; CON6 2(AVDD0)* 3(VDD0)* 5(VCOM0)* 6(VDD1)* 8(V14)* 9(V13)* 10(V12)* 11(V11)* 12(V10)* 13(V9)* 14(V8)* 16(VDD_LVDS)* 34(GRB)* 35(STBYB)* 36(SHLR)* 37(VDD2)* 38(UPND)* 40(AVDD1)* 41(VCOM1)* 42(DITH)* 44(VDD3)* 46(V7)* 47(V6)* 48(V5)* 49(V4)* 50(V3)* 51(V2)* 52(V1)* 54(VDD4)* 56(VGH)* 57(VDD5)* 58(VGL)* 60(NC)*; J1 3(SHIELD)*; J2 2*; SW2 2* 4(6)*; U1 A19(TWI4_SCK/PI2)* A20(TWI3_SCK/PI0)* AA16(VRP_TVIN)* AA22(X2_TP)* AA23(Y2_TP)* AB17(TVOUT3)* AB20(LINEINL)* AB21(LINEINR)* AB22(LRADC1)* AC21(MICIN2)* AC22(PHOUTP)* AC23(PHOUTN)* B20(TWI3_SDA/PI1)* C1(LCD1_D17/ETXD0/KP_IN7/SMC_VCCEN/EINT17/CSI1_D17/PH17)* C3(LCD1_D12/PS2_SCK1/EINT12/CSI1_D12/PH12)* C10(I2S_DO3/PB11)* C11(I2S_DO2/PB10)* C15(PS2_SCK1/TCLKIN0/EINT26/SPI0_CS1/PI14)* C17(SPI0_CS0/UART5_TX/EINT22/PI10)* D2(LCD1_D20/ERXDV/CAN_TX/EINT20/CSI1_D20/PH20)* D15(PS2_SDA1/TCLKIN1/EINT27/SPI1_CS1/PI15)* D16(SPI0_MISO/UART6_RX/CLK_OUT_B/EINT25/PI13)* D17(SPI0_CLK/UART5_RX/EINT23/PI11)* E1(LCD1_D22/EMDIO/KP_OUT2/SDC1_CMD/CSI1_D22/PH22)* E2(LCD1_D23/ETXEN/KP_OUT3/SDC1_CLK/CSI1_D23/PH23)* E3(LCD1_CLK/ETXCK/KP_OUT4/SDC1_D0/CSI1_PCLK/PH24)* E4(LCD1_DE/ECRS/KP_OUT5/SDC1_D1/CSI1_FIELD/PH25)* F3(LCD1_HSYNC/ECOL/KP_OUT6/SDC1_D2/CSI1_HSYNC/PH26)* F4(LCD1_VSYNC/ETXERR/KP_OUT7/SDC1_D3/CSI1_VSYNC/PH27)* G19(SPI0_CS0/PC23)* J3(SCK1#)* J4(SCK1)* J20(NCE7/SPI2_MISO/PC22)* J21(NCE6/SPI2_MOSI/PC21)* K21(NCE5/SPI2_CLK/PC20)* L21(NCE4/SPI2_CS0/PC19)* M21(NWP/PC16)* N8(SADBG)* P8(SDDBG0)* P19(CLKM_SATA)* P20(DM1)* P21(DP1)* R8(SDDBG1)* R14(NC1)* R15(PLLVREG)* R16(NC0)* R19(CLKP_SATA)* T14(VREG1_HDMI)* T15(PLLTEST)* T16(PLLDV)* T20(TXP_SATA)* T21(TXM_SATA)* U20(RXM_SATA)* U21(RXP_SATA)* V21(REXT_SATA)* Y16(VRN_TVIN)* Y20(FMINL)* Y21(FMINR)* Y22(X1_TP)* Y23(Y1_TP)*; U9 3(GPIO3)* 29(DC3SET)* 30(BACKUP)*; U12 6(NC)*; U27 4(FM_RX)* 5(N_WAKE)* 8(BT_VIO/N_HOST_WAKE) 32(GPS_RF)* 35(N_I2C_SDA)* 37(N_I2C_SCL)* 38(N_REG_PU)* 39(TX2)* 40(TX1)* 45(N_VDDSWPIO)* 46(N_VDDSWP_OUT)* 47(N_VDDSWP_IN)*

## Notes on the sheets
sheet 1
- POWER-DC/DC
- R1           R2
- R1           R2
- Vout = 0.6*(1+R1/R2)
- Vout = 0.6*(1+R1/R2)
- R3
- R4
- Vout = 0.6*(1+R3/R4)
sheet 2
- CPU2
- 注意：PA剩余口全部
  过孔接地，用于散热。
sheet 3
- USB-USB OTG
- Differential pairs
  Z0= 90 ohm
- 如加ESD器件,
  取消该电阻，
  直接短接。
- Ilim (A)=6800/Rset (ohm)
sheet 4
- LCD
- Option
  在使用功耗
  大的屏时使
  用100uF,其
  余情况可使
  用10uF。
- 对于9.7”及以上屏的方案，需要在ACIN和BAT
  做外部通路，防止PMU承受过大电流而损坏。
  1.使用9.7”以下屏将电阻A贴上，B部分器件不贴；
  2.使用9.7”以上屏将电阻A不贴，B部分器件贴上。
- A
- 仅供参考
  Vfb = 100mv : LSR1  = 73K
  Vfb = 150mv : LSR1  = 47K
  Vfb = 200mv : LSR1  = 33K
  Vfb = 250mv : LSR1  = 25K
  Vfb = 300mv : LSR1  = 20K
  Vfb = 350mv : LSR1  = 16K
- B
- Option
  LVDS连接示意图
sheet 5
- CPU1
sheet 6
- BLOCK
- Option
- 16bit*2
- LCD Display &Touch
- HD Video Display
- Option:LCD MIPI
- DDR3 DRAM
  8bit*4
- LVDS Display
- 32.768K
  Crystal
- Nand &
  eMMC
- 24M
  Crystal
- Option
- IIC
- Capacitive Touch
  Screen Controller
- Option
- Touch Controller
- Head Phone
- Audio  Input
- Audio ADC0
- LCD Controller
- Microphone
- HP
  AMP
- Audio Output
- Audio DAC
- LVDS Controller
- HDMI Port
- Class D
    AMP
- HDMI 1.4
- A20
  DUAL CORE
- G-Sensor
- IIC
- TV-OUT
- Video DAC
- Video
- CSI0
- Video Port1
- Rear camera
- USB0 OTG 1.1&2.0
- M
- USB1 EHCI/OHCI
- USB2 EHCI/OHCI
- Card Controller3
- Motor
- IR Controller
- CSI1
- Video Port2
- Front camera
- ADC
- Card Controller0
- Plug
- ~
- 5V
- IIC
- PMU AXP209
  (System Power)
- USB2 WIFI
- AC Adapter
- USB0 OTG
- Slot0
- WIFI+BT
- Key
- AC Line
- IR
- Power Management
- Battery
  Voltage Supply 3.55V-4.20V
- USB Port0
- SD/MMC
  Card
sheet 7
- Notes：Unless Otherwise Stated
- Scheme Spec：
- Schematics Index：
- FLASH: MLC,  3V
- P01: COVER
  P02: BLOCK
  P03: PIO ASSIGNMENT
  P04: POWER TREE
  P05: CPU1
  P06: CPU2
  P07: DDR3 8bit x 4pcs
  P08: DDR3 16bit x 2pcs
  P09: BESIDE CPU
  P10: POWER1
  P11: POWER2
  P12: NAND&eMMC
  P13: HDMI-CSI
  P14: KEY-IR-TVOUT-MT
  P15: CARD-DEBUG-GS
  P16: LCD
  P17: WIFI+BT
  P18: USB
  P19: HP-MIC-SPK
  P20: LCD MIPI 7"85
- DRAM:  DDR3, 1.5V
- Key:   Vol+,Vol-,MENU,SEARCH,HOME,ESC,ENTER
- Power: DCIN， 5V，2A；BAT，4.2V
- USB0:  OTG
- USB2:  WIFI
- WIFI:  USB WIFI&SDIO WIFI+BT
- Card:  TFcard
- Other:  Headphone, MIC, G-Sensor,Camera
- Power Supply：
- Name
- Vout
- Imax
- Use
- 1.25V
- AXP209 DCDC2
- 1600mA
- CPU
- AXP209 DCDC3
- 1.2V
- 1200mA
- CORE
- AXP209 LDO1
- 1.3V
- 30mA
- RTC
- AVCC
- AXP209 LDO2
- 3V
- 200mA
- AXP209 LDO3
- 2.8V
- 400mA
- CSI0-IO
- AXP209 LDO4
- 2.8V
- 200mA
- CSI1-IO
- AP2125 LDO
- 1.8V
- 300mA
- CSI-DVDD
- AP3410 DCDC
- 1.5V
- 1200mA
- DRAM
- AP3410 DCDC
- 3V
- 1200mA
- VCC/LCD/NAND//WIFI
- SY7208
- 5V
- 1000mA
- HDMI/USB
- AP2125 LDO
- 300mA
- WIFI
- 3.3V
- AP3032 DCDC
- 1400mA
- LCD
- AP3032 DCDC
- 1400mA
- LCD
- AP3032 DCDC
- 1400mA
- LCD MIPI
- Rev
- Description
- Date
- Drawn
- Checked
- Approved
- A20_PAD_STD_V1.0
- 2013-01-30
- A20_PAD_STD_V1.1
- 2013-04-01
- Dennislo
- A20_PAD_STD_V1.2
- 2013-08-15
- Dennislo
sheet 8
- POWER-PMU
- 1、ACIN电源网络保留给LCD供电；
  2、在ACIN、VBUS上靠近PMU接10uF电容滤波。
- POWER LINE:Width>=80mil
- POWER LINE:Width>=40mil
- POWER INPUT
- 靠近LDO3IN放置
- 靠近VIN1放置
- DCDC3网络为反馈网络，
  lay板时走细线即可。
- CSI-IOVDD =2.8V
- CSI-AVDD  =2.8V
- DCDC2网络为反馈网络，
  lay板时走细线即可。
- 所选用的二极管在环境
  温度75摄氏度时反向漏
  电要小于 5uA。
- 需指示充电状态以及电源状态时，增加上
- 此时不支持电池温度检测
- 注意：
  1、在没有ACIN插座，只使用USB供电时，
     把A部分器件贴上;
  2、有ACIN时A部分器件不贴。
- 备注：
  对于电感尺寸有轻薄要求的，推荐使用乾坤的
  PSE250201B-2R2MS,其体积为2.6x2.1平方毫米，
  饱和电流为1.8A,直流阻抗为85毫欧。
- A
sheet 9
- POWER TREE
- LAYOUT：ACIN、BATT、IPSOUT输入或
  输出线，从PMU管脚处就要保证尽量粗。
- ACIN(5V)2A
- DC/DC2-1.25V-1.6A
- for CPU
- Battery
  charger
  /detect
- DC/DC3-1.2V-1.2A
- INTERFACE/HDMI
- USBVBUS
  （5V-900mA）
- AXP209
- LDO1-1.3V-30mA
- RTC-VDD
- BAT(4.2V)
- LDO2-3.00V-200mA
- AVCC
- LDO3-2.80V-400mA
- CSI-IOVDD
- IPSOUT
  3.3V-5V-2A
- LDO4-1.25V-3.3V-200mA
- CSI-AVDD
- AP3410
- AP3410
- AP2125
- AP2125
- SY7152
- AP3032
- AP3032
- AP3032
- SY8088
- SY8088
- SY7200A
- SY7200A
- Option
- 1V5
- 1000mA
- 3V
- 1000mA
- 3V3
- 300mA
- 1V8
- 300mA
- 5V
- 1000mA
- 提供了可以pin
  对pin替换的电
  源IC.
- LCD
- DRAM-VCC
- INTERFACE
- WIFI
- CSI
- USB OTG
- HDMI
- LCD BL
- LCD BIAS
- MIPI BL
sheet 10
- HDMI-CSI
- HDMI
- Differential pairs
  Z0= 100 ohm
- LAYOUT差分走线过孔不
  能超过2个，有完整铺地。
- CSI0-BACK
- 200W-后置高分辨率
- CSI1-FRONT
- 30W-前置低分辨率
- CSI-IOVDD =2.8V
- CSI-AVDD  =2.8V
- CSI-DVDD   =1.8V
- 要求上拉
- 要求上拉
- 300mA
- 1.8V&1.5V
- 1、LAYOUT时，请保证摄像头成像方向
  与LCD显示一致；
  2、LAYOUT时，请尽量保证两个摄像头
  的连接器不要分开太远，保证电源以及
  信号到达CSI的一致性；
  3、若选用其他模组，请检查CSI-IOVDD,
  CSI-AVDD,CSI-DVDD的具体电压值以及
  负载能力能够满足。
sheet 11
- WIFI-BT
- WiFi ANT
- 50 Ohm RF trace
- AP6210需要框内A和B部分,R131,R132就NC
- AP6181只需要框内A部分
- B
- A
- L1, rated current 700mA
  expectation specification.
- AP6210接上此电阻,AP6181不接
- USB  WIFI
- 300mA
- 3.3V
- A
- Differential pairs
  Z0= 90 ohm
- 电容A请放在模组距离5mm之内，
  电容A位贴0欧电阻也可以
- PAD_A10_STD
